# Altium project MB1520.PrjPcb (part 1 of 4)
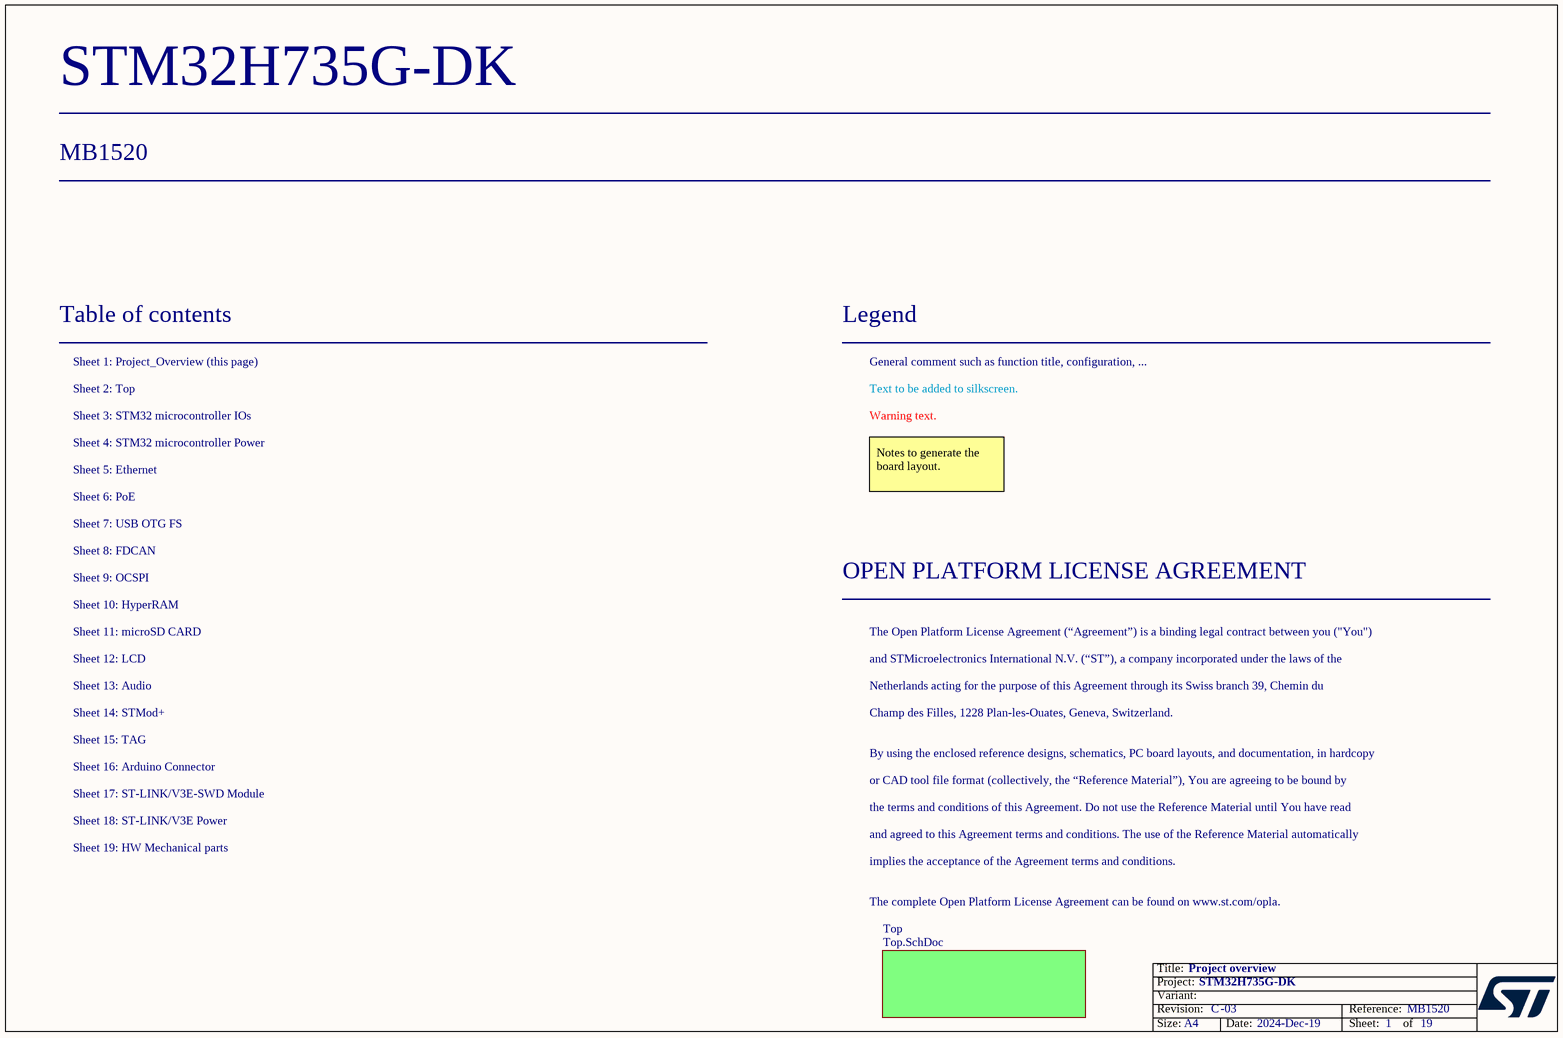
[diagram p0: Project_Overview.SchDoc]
Board_Reference: MB1520; Board_PCB_Revision: C; Board_Name: STM32H735G-DK; Board_Document_Date: 2024-Dec-19; Board_Assembly_Revision: 03
19 sheets, 477 parts. Net scope: flat (ports and power ports of the same name join across sheets).
Board file: MB1520.PcbDoc
Sheets:
  Project_Overview.SchDoc
    Top = Top.SchDoc
      Power = STM32_microcontroller_Power.SchDoc
      TAG = TAG.SchDoc
      Audio = Audio.SchDoc
      USB_OTG_FS = USB_OTG_FS.SchDoc
      Arduino = Arduino_Connector.SchDoc
      STMod+ = STMod+.SchDoc
      U_MCU = STM32_microcontroller_IOs.SchDoc
      U_Ethernet = Ethernet.SchDoc
        PoE = PoE.SchDoc
      FDCANs = FDCAN.SchDoc
      STlink_V3E_Module = STlink_V3E_Module.SchDoc
      STlink_V3E_PWR = STlink_V3E_PWR.SchDoc
      HW_Mechanical_Parts = HW_Mechanical_Parts.SchDoc
      U_OCSPI = OCSPI.SchDoc
      U_LCD = LCD.SchDoc
      U_HyperRAM = HyperRAM.SchDoc
      U_SD CARD = SD_CARD.SchDoc

## Sheet Project_Overview.SchDoc: Project overview
size A4; Date: Not used; ApprovedBy: Not used; CheckedBy: Not used; Author: Not used; CompanyName: STMicroelectronics; DrawnBy: Not used; Engineer: Not used; Organization: Not used; Address1: Not used; Address2: Not used; Address3: Not used; Address4: Not used; DocumentNumber: Not used; Revision: Not used; SheetNumber: 1; SheetTotal: 19

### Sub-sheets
Top = Top.SchDoc: no entries

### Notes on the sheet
- Table of contents
- Sheet 1: Project_Overview (this page)
- Legend
- General comment such as function title, configuration, ...
- Sheet 2: Top
- Sheet 4: STM32 microcontroller Power
- Sheet 3: STM32 microcontroller IOs
- Text to be added to silkscreen.
- Warning text.
- Sheet 6: PoE
- Sheet 5: Ethernet
- Notes to generate the board layout.
- Sheet 8: FDCAN
- Sheet 7: USB OTG FS
- Sheet 9: OCSPI
- OPEN PLATFORM LICENSE AGREEMENT
- Sheet 10: HyperRAM
- Sheet 11: microSD CARD
- The Open Platform License Agreement (“Agreement”) is a binding legal contract between you ("You")
- Sheet 12: LCD
- Sheet 14: STMod+
- Sheet 13: Audio
- and STMicroelectronics International N.V. (“ST”), a company incorporated under the laws of the
- Netherlands acting for the purpose of this Agreement through its Swiss branch 39, Chemin du
- Champ des Filles, 1228 Plan-les-Ouates, Geneva, Switzerland.
- Sheet 16: Arduino Connector
- Sheet 15: TAG
- By using the enclosed reference designs, schematics, PC board layouts, and documentation, in hardcopy
- or CAD tool file format (collectively, the “Reference Material”), You are agreeing to be bound by
- Sheet 18: ST-LINK/V3E Power
- Sheet 17: ST-LINK/V3E-SWD Module
- Sheet 19: HW Mechanical parts
- the terms and conditions of this Agreement. Do not use the Reference Material until You have read
- and agreed to this Agreement terms and conditions. The use of the Reference Material automatically
- implies the acceptance of the Agreement terms and conditions.
- The complete Open Platform License Agreement can be found on www.st.com/opla.

## Sheet Top.SchDoc: TOP
size A3; Date: Not used; ApprovedBy: Not used; CheckedBy: Not used; Author: Not used; CompanyName: STMicroelectronics; DrawnBy: Not used; Engineer: Not used; Organization: Not used; Address1: Not used; Address2: Not used; Address3: Not used; Address4: Not used; DocumentNumber: Not used; Revision: Not used; SheetNumber: 2; SheetTotal: 19
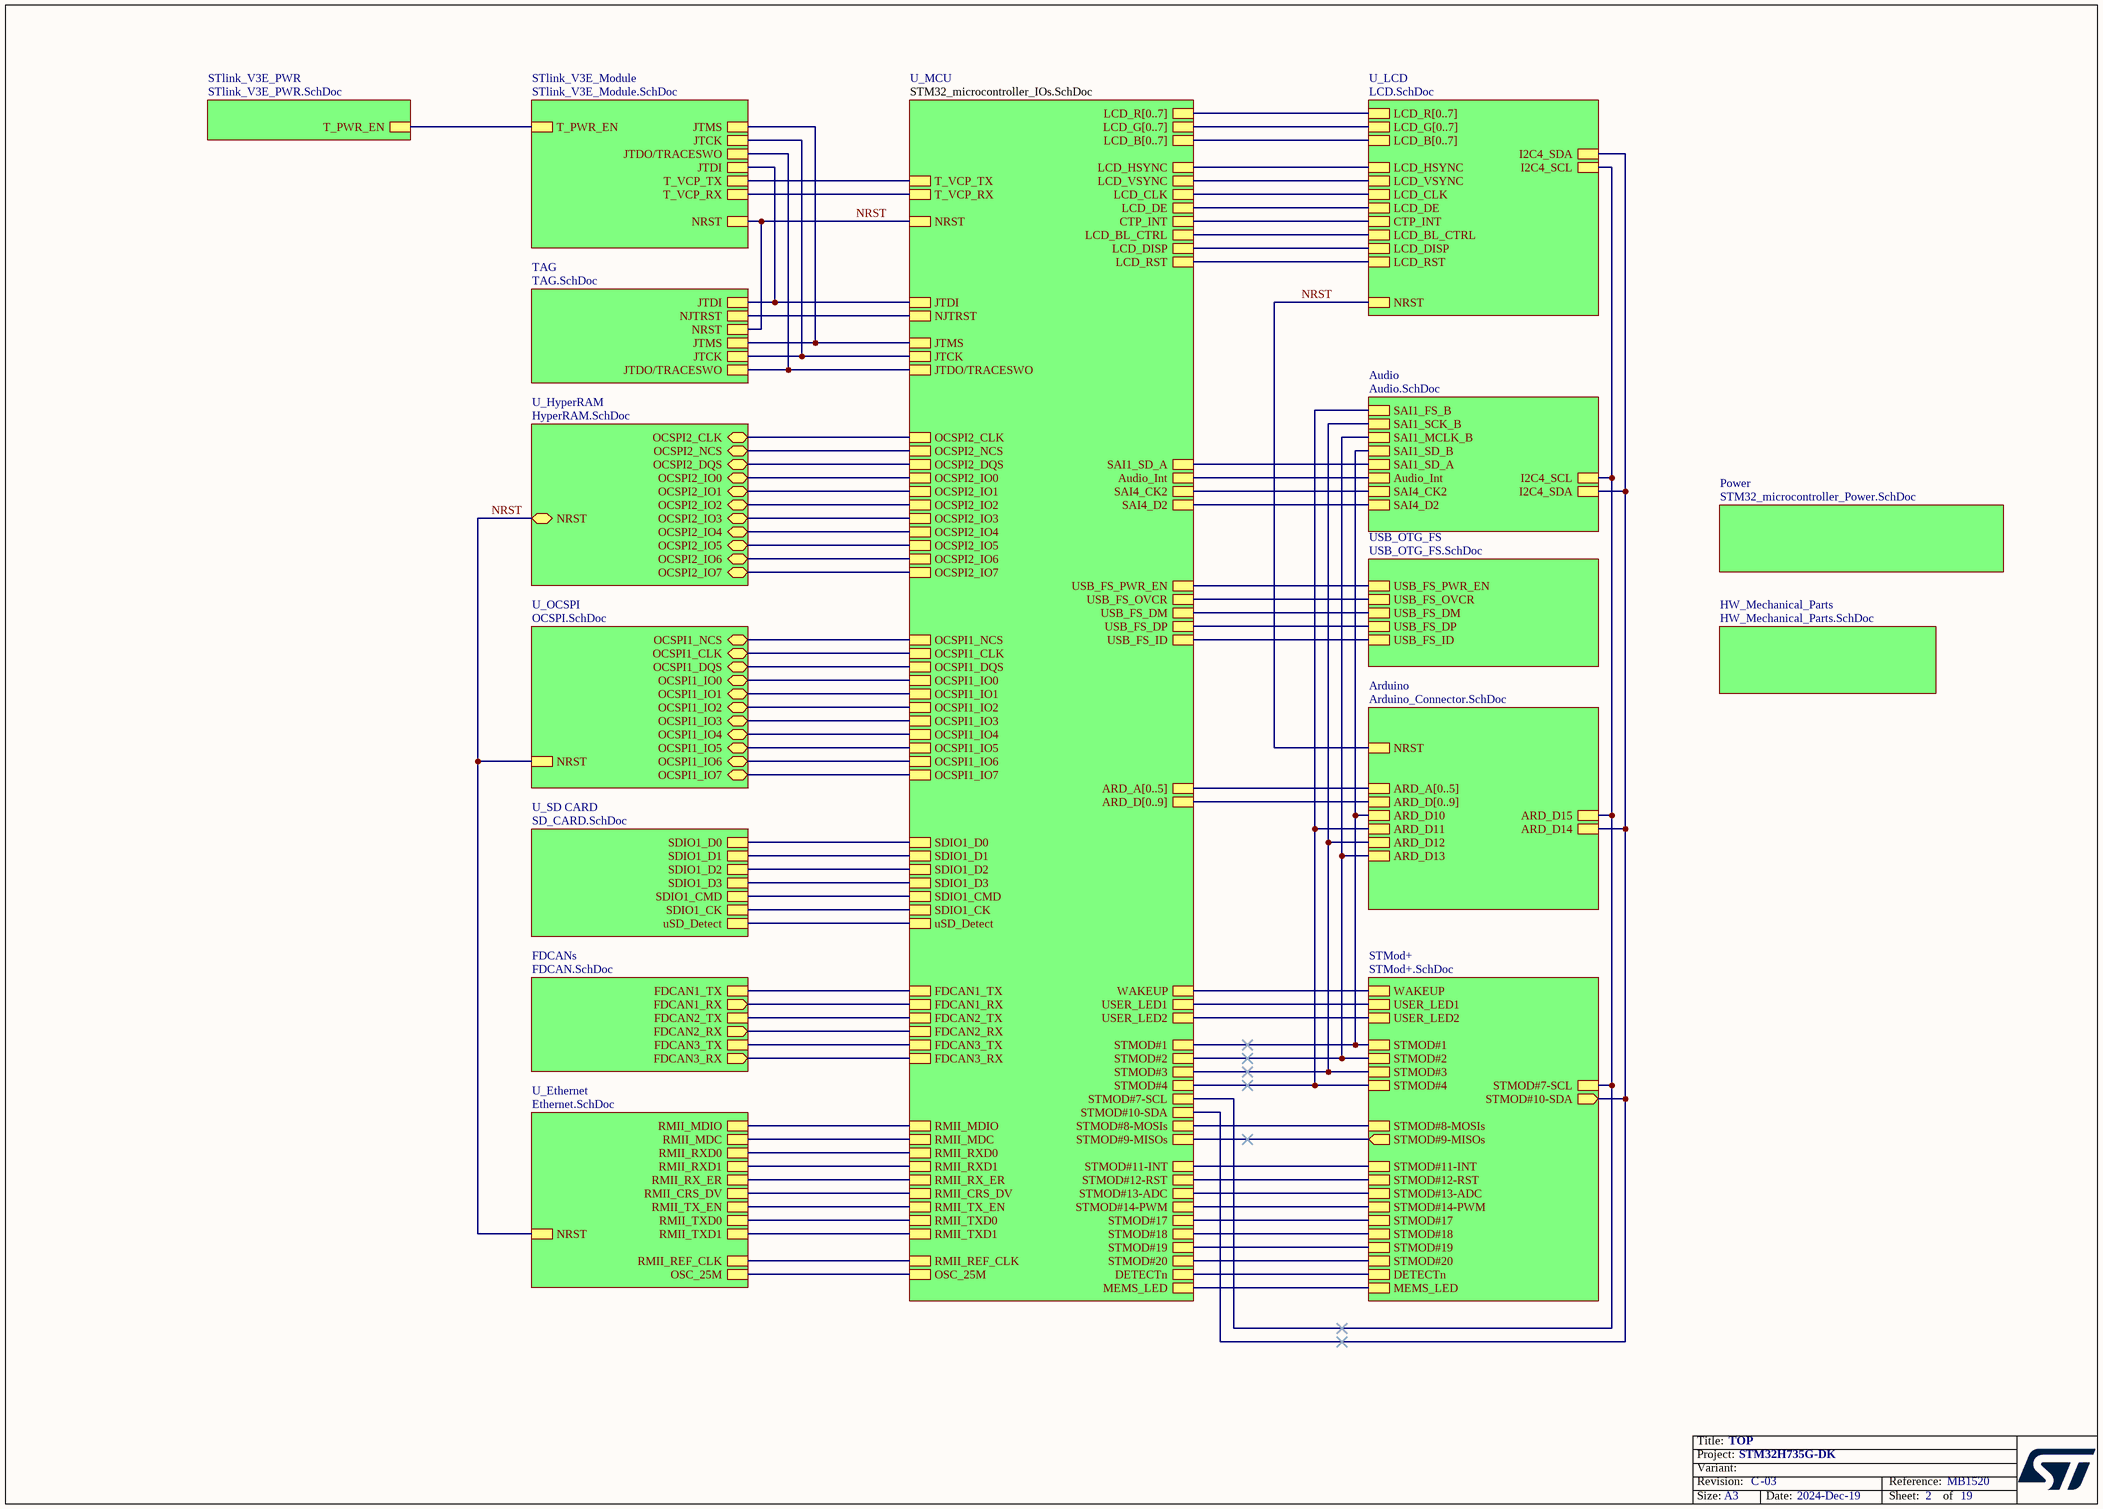
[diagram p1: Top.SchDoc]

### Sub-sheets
Arduino = Arduino_Connector.SchDoc: ARD_D13, ARD_D12, ARD_D11, ARD_D10, ARD_D15, ARD_D14, ARD_A[0..5], ARD_D[0..9], NRST
Audio = Audio.SchDoc: I2C4_SCL, I2C4_SDA, SAI1_SCK_B, SAI1_FS_B, SAI1_SD_B, SAI1_SD_A, Audio_Int, SAI1_MCLK_B, SAI4_D2, SAI4_CK2
FDCANs = FDCAN.SchDoc: FDCAN1_TX, FDCAN2_TX, FDCAN3_TX, FDCAN1_RX (out), FDCAN3_RX (out), FDCAN2_RX (out)
HW_Mechanical_Parts = HW_Mechanical_Parts.SchDoc: no entries
Power = STM32_microcontroller_Power.SchDoc: no entries
STlink_V3E_Module = STlink_V3E_Module.SchDoc: T_PWR_EN, T_VCP_TX, T_VCP_RX, JTDO/TRACESWO, JTMS, JTCK, NRST, JTDI
STlink_V3E_PWR = STlink_V3E_PWR.SchDoc: T_PWR_EN
STMod+ = STMod+.SchDoc: STMOD#8-MOSIs, STMOD#14-PWM, STMOD#19, STMOD#20, STMOD#17, STMOD#18, STMOD#1, STMOD#3, STMOD#2, STMOD#4, WAKEUP, USER_LED1, USER_LED2, STMOD#7-SCL, STMOD#10-SDA (out), STMOD#9-MISOs (out), STMOD#12-RST, STMOD#13-ADC, STMOD#11-INT, DETECTn, MEMS_LED
TAG = TAG.SchDoc: JTDO/TRACESWO, JTDI, NJTRST, JTMS, JTCK, NRST
U_Ethernet = Ethernet.SchDoc: OSC_25M, RMII_MDIO, RMII_MDC, RMII_RXD1, RMII_TXD1, RMII_CRS_DV, RMII_RX_ER, RMII_RXD0, RMII_REF_CLK, RMII_TX_EN, RMII_TXD0, NRST
U_HyperRAM = HyperRAM.SchDoc: OCSPI2_NCS (bidir), NRST (bidir), OCSPI2_CLK (bidir), OCSPI2_DQS (bidir), OCSPI2_IO0 (bidir), OCSPI2_IO3 (bidir), OCSPI2_IO1 (bidir), OCSPI2_IO2 (bidir), OCSPI2_IO5 (bidir), OCSPI2_IO4 (bidir), OCSPI2_IO7 (bidir), OCSPI2_IO6 (bidir)
U_LCD = LCD.SchDoc: LCD_R[0..7], I2C4_SDA, I2C4_SCL, LCD_B[0..7], LCD_G[0..7], LCD_HSYNC, LCD_VSYNC, LCD_CLK, LCD_DE, CTP_INT, LCD_BL_CTRL, LCD_DISP, NRST, LCD_RST
U_MCU = STM32_microcontroller_IOs.SchDoc: STMOD#14-PWM, STMOD#20, USB_FS_ID, SDIO1_CK, SDIO1_CMD, LCD_DE, LCD_CLK, CTP_INT, USER_LED1, USER_LED2, ARD_A[0..5], ARD_D[0..9], LCD_R[0..7], LCD_G[0..7], LCD_B[0..7], FDCAN3_RX, FDCAN3_TX, T_VCP_TX, T_VCP_RX, FDCAN2_RX, FDCAN2_TX, FDCAN1_TX, FDCAN1_RX, LCD_DISP, LCD_VSYNC, LCD_BL_CTRL, LCD_HSYNC, JTDI, JTDO/TRACESWO, NJTRST, JTCK, JTMS, OCSPI2_NCS, OCSPI1_DQS, OCSPI1_NCS, OCSPI1_CLK, OCSPI2_DQS, OSC_25M, USB_FS_DP, USB_FS_DM, USB_FS_OVCR, USB_FS_PWR_EN, WAKEUP, SAI1_SD_A, SAI4_D2, SAI4_CK2, Audio_Int, STMOD#1, STMOD#2, STMOD#3, STMOD#4, STMOD#19, STMOD#17, STMOD#18, STMOD#10-SDA, STMOD#7-SCL, STMOD#8-MOSIs, STMOD#9-MISOs, STMOD#11-INT, STMOD#13-ADC, STMOD#12-RST, MEMS_LED, DETECTn, uSD_Detect, RMII_RXD1, RMII_RXD0, RMII_CRS_DV, RMII_RX_ER, RMII_TX_EN, RMII_TXD0, RMII_TXD1, RMII_MDIO, RMII_MDC, RMII_REF_CLK, SDIO1_D1, SDIO1_D0, SDIO1_D2, SDIO1_D3, OCSPI2_CLK, NRST, OCSPI1_IO7, OCSPI1_IO4, OCSPI1_IO5, OCSPI1_IO0, OCSPI1_IO1, OCSPI1_IO3, OCSPI1_IO2, OCSPI1_IO6, OCSPI2_IO7, OCSPI2_IO6, OCSPI2_IO5, OCSPI2_IO0, OCSPI2_IO2, OCSPI2_IO1, OCSPI2_IO4, OCSPI2_IO3, LCD_RST
U_OCSPI = OCSPI.SchDoc: OCSPI1_NCS (bidir), OCSPI1_CLK (bidir), NRST, OCSPI1_DQS (bidir), OCSPI1_IO0 (bidir), OCSPI1_IO1 (bidir), OCSPI1_IO2 (bidir), OCSPI1_IO3 (bidir), OCSPI1_IO4 (bidir), OCSPI1_IO5 (bidir), OCSPI1_IO6 (bidir), OCSPI1_IO7 (bidir)
U_SD CARD = SD_CARD.SchDoc: SDIO1_CK, SDIO1_CMD, uSD_Detect, SDIO1_D1, SDIO1_D0, SDIO1_D2, SDIO1_D3
USB_OTG_FS = USB_OTG_FS.SchDoc: USB_FS_ID, USB_FS_PWR_EN, USB_FS_OVCR, USB_FS_DM, USB_FS_DP

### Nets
NRST: sheet TAG/NRST, sheet Arduino/NRST, sheet U_MCU/NRST, sheet U_Ethernet/NRST, sheet STlink_V3E_Module/NRST, sheet U_OCSPI/NRST, sheet U_LCD/NRST, sheet U_HyperRAM/NRST
(unnamed): sheet TAG/JTDO/TRACESWO, sheet U_MCU/JTDO/TRACESWO, sheet STlink_V3E_Module/JTDO/TRACESWO
(unnamed): sheet TAG/JTDI, sheet U_MCU/JTDI, sheet STlink_V3E_Module/JTDI  [a separate net that carries the same name]
(unnamed): sheet TAG/NJTRST, sheet U_MCU/NJTRST  [a separate net that carries the same name]
(unnamed): sheet TAG/JTMS, sheet U_MCU/JTMS, sheet STlink_V3E_Module/JTMS  [a separate net that carries the same name]
(unnamed): sheet TAG/JTCK, sheet U_MCU/JTCK, sheet STlink_V3E_Module/JTCK  [a separate net that carries the same name]
(unnamed): sheet Audio/I2C4_SCL, sheet Arduino/ARD_D15, sheet STMod+/STMOD#7-SCL, sheet U_MCU/STMOD#7-SCL, sheet U_LCD/I2C4_SCL  [a separate net that carries the same name]
(unnamed): sheet Audio/I2C4_SDA, sheet Arduino/ARD_D14, sheet STMod+/STMOD#10-SDA, sheet U_MCU/STMOD#10-SDA, sheet U_LCD/I2C4_SDA  [a separate net that carries the same name]
(unnamed): sheet Audio/SAI1_SCK_B, sheet Arduino/ARD_D12, sheet STMod+/STMOD#3, sheet U_MCU/STMOD#3  [a separate net that carries the same name]
(unnamed): sheet Audio/SAI1_FS_B, sheet Arduino/ARD_D11, sheet STMod+/STMOD#4, sheet U_MCU/STMOD#4  [a separate net that carries the same name]
(unnamed): sheet Audio/SAI1_SD_B, sheet Arduino/ARD_D10, sheet STMod+/STMOD#1, sheet U_MCU/STMOD#1  [a separate net that carries the same name]
(unnamed): sheet Audio/SAI1_SD_A, sheet U_MCU/SAI1_SD_A  [a separate net that carries the same name]
(unnamed): sheet Audio/Audio_Int, sheet U_MCU/Audio_Int  [a separate net that carries the same name]
(unnamed): sheet Audio/SAI1_MCLK_B, sheet Arduino/ARD_D13, sheet STMod+/STMOD#2, sheet U_MCU/STMOD#2  [a separate net that carries the same name]
(unnamed): sheet Audio/SAI4_D2, sheet U_MCU/SAI4_D2  [a separate net that carries the same name]
(unnamed): sheet Audio/SAI4_CK2, sheet U_MCU/SAI4_CK2  [a separate net that carries the same name]
(unnamed): sheet USB_OTG_FS/USB_FS_ID, sheet U_MCU/USB_FS_ID  [a separate net that carries the same name]
(unnamed): sheet USB_OTG_FS/USB_FS_PWR_EN, sheet U_MCU/USB_FS_PWR_EN  [a separate net that carries the same name]
(unnamed): sheet USB_OTG_FS/USB_FS_OVCR, sheet U_MCU/USB_FS_OVCR  [a separate net that carries the same name]
(unnamed): sheet USB_OTG_FS/USB_FS_DM, sheet U_MCU/USB_FS_DM  [a separate net that carries the same name]
(unnamed): sheet USB_OTG_FS/USB_FS_DP, sheet U_MCU/USB_FS_DP  [a separate net that carries the same name]
(unnamed): sheet STMod+/STMOD#8-MOSIs, sheet U_MCU/STMOD#8-MOSIs  [a separate net that carries the same name]
(unnamed): sheet STMod+/STMOD#14-PWM, sheet U_MCU/STMOD#14-PWM  [a separate net that carries the same name]
(unnamed): sheet STMod+/STMOD#19, sheet U_MCU/STMOD#19  [a separate net that carries the same name]
(unnamed): sheet STMod+/STMOD#20, sheet U_MCU/STMOD#20  [a separate net that carries the same name]
(unnamed): sheet STMod+/STMOD#17, sheet U_MCU/STMOD#17  [a separate net that carries the same name]
(unnamed): sheet STMod+/STMOD#18, sheet U_MCU/STMOD#18  [a separate net that carries the same name]
(unnamed): sheet STMod+/WAKEUP, sheet U_MCU/WAKEUP  [a separate net that carries the same name]
(unnamed): sheet STMod+/USER_LED1, sheet U_MCU/USER_LED1  [a separate net that carries the same name]
(unnamed): sheet STMod+/USER_LED2, sheet U_MCU/USER_LED2  [a separate net that carries the same name]
(unnamed): sheet STMod+/STMOD#9-MISOs, sheet U_MCU/STMOD#9-MISOs  [a separate net that carries the same name]
(unnamed): sheet STMod+/STMOD#12-RST, sheet U_MCU/STMOD#12-RST  [a separate net that carries the same name]
(unnamed): sheet STMod+/STMOD#13-ADC, sheet U_MCU/STMOD#13-ADC  [a separate net that carries the same name]
(unnamed): sheet STMod+/STMOD#11-INT, sheet U_MCU/STMOD#11-INT  [a separate net that carries the same name]
(unnamed): sheet STMod+/DETECTn, sheet U_MCU/DETECTn  [a separate net that carries the same name]
(unnamed): sheet STMod+/MEMS_LED, sheet U_MCU/MEMS_LED  [a separate net that carries the same name]
(unnamed): sheet U_MCU/SDIO1_CK, sheet U_SD CARD/SDIO1_CK  [a separate net that carries the same name]
(unnamed): sheet U_MCU/SDIO1_CMD, sheet U_SD CARD/SDIO1_CMD  [a separate net that carries the same name]
(unnamed): sheet U_MCU/LCD_DE, sheet U_LCD/LCD_DE  [a separate net that carries the same name]
(unnamed): sheet U_MCU/LCD_CLK, sheet U_LCD/LCD_CLK  [a separate net that carries the same name]
(unnamed): sheet U_MCU/CTP_INT, sheet U_LCD/CTP_INT  [a separate net that carries the same name]
(unnamed): sheet U_MCU/FDCAN3_RX, sheet FDCANs/FDCAN3_RX  [a separate net that carries the same name]
(unnamed): sheet U_MCU/FDCAN3_TX, sheet FDCANs/FDCAN3_TX  [a separate net that carries the same name]
(unnamed): sheet U_MCU/T_VCP_TX, sheet STlink_V3E_Module/T_VCP_TX  [a separate net that carries the same name]
(unnamed): sheet U_MCU/T_VCP_RX, sheet STlink_V3E_Module/T_VCP_RX  [a separate net that carries the same name]
(unnamed): sheet U_MCU/FDCAN2_RX, sheet FDCANs/FDCAN2_RX  [a separate net that carries the same name]
(unnamed): sheet U_MCU/FDCAN2_TX, sheet FDCANs/FDCAN2_TX  [a separate net that carries the same name]
(unnamed): sheet U_MCU/FDCAN1_TX, sheet FDCANs/FDCAN1_TX  [a separate net that carries the same name]
(unnamed): sheet U_MCU/FDCAN1_RX, sheet FDCANs/FDCAN1_RX  [a separate net that carries the same name]
(unnamed): sheet U_MCU/LCD_DISP, sheet U_LCD/LCD_DISP  [a separate net that carries the same name]
(unnamed): sheet U_MCU/LCD_VSYNC, sheet U_LCD/LCD_VSYNC  [a separate net that carries the same name]
(unnamed): sheet U_MCU/LCD_BL_CTRL, sheet U_LCD/LCD_BL_CTRL  [a separate net that carries the same name]
(unnamed): sheet U_MCU/LCD_HSYNC, sheet U_LCD/LCD_HSYNC  [a separate net that carries the same name]
(unnamed): sheet U_MCU/OCSPI2_NCS, sheet U_HyperRAM/OCSPI2_NCS  [a separate net that carries the same name]
(unnamed): sheet U_MCU/OCSPI1_DQS, sheet U_OCSPI/OCSPI1_DQS  [a separate net that carries the same name]
(unnamed): sheet U_MCU/OCSPI1_NCS, sheet U_OCSPI/OCSPI1_NCS  [a separate net that carries the same name]
(unnamed): sheet U_MCU/OCSPI1_CLK, sheet U_OCSPI/OCSPI1_CLK  [a separate net that carries the same name]
(unnamed): sheet U_MCU/OCSPI2_DQS, sheet U_HyperRAM/OCSPI2_DQS  [a separate net that carries the same name]
(unnamed): sheet U_MCU/OSC_25M, sheet U_Ethernet/OSC_25M  [a separate net that carries the same name]
(unnamed): sheet U_MCU/uSD_Detect, sheet U_SD CARD/uSD_Detect  [a separate net that carries the same name]
(unnamed): sheet U_MCU/RMII_RXD1, sheet U_Ethernet/RMII_RXD1  [a separate net that carries the same name]
(unnamed): sheet U_MCU/RMII_RXD0, sheet U_Ethernet/RMII_RXD0  [a separate net that carries the same name]
(unnamed): sheet U_MCU/RMII_CRS_DV, sheet U_Ethernet/RMII_CRS_DV  [a separate net that carries the same name]
(unnamed): sheet U_MCU/RMII_RX_ER, sheet U_Ethernet/RMII_RX_ER  [a separate net that carries the same name]
(unnamed): sheet U_MCU/RMII_TX_EN, sheet U_Ethernet/RMII_TX_EN  [a separate net that carries the same name]
(unnamed): sheet U_MCU/RMII_TXD0, sheet U_Ethernet/RMII_TXD0  [a separate net that carries the same name]
(unnamed): sheet U_MCU/RMII_TXD1, sheet U_Ethernet/RMII_TXD1  [a separate net that carries the same name]
(unnamed): sheet U_MCU/RMII_MDIO, sheet U_Ethernet/RMII_MDIO  [a separate net that carries the same name]
(unnamed): sheet U_MCU/RMII_MDC, sheet U_Ethernet/RMII_MDC  [a separate net that carries the same name]
(unnamed): sheet U_MCU/RMII_REF_CLK, sheet U_Ethernet/RMII_REF_CLK  [a separate net that carries the same name]
(unnamed): sheet U_MCU/SDIO1_D1, sheet U_SD CARD/SDIO1_D1  [a separate net that carries the same name]
(unnamed): sheet U_MCU/SDIO1_D0, sheet U_SD CARD/SDIO1_D0  [a separate net that carries the same name]
(unnamed): sheet U_MCU/SDIO1_D2, sheet U_SD CARD/SDIO1_D2  [a separate net that carries the same name]
(unnamed): sheet U_MCU/SDIO1_D3, sheet U_SD CARD/SDIO1_D3  [a separate net that carries the same name]
(unnamed): sheet U_MCU/OCSPI2_CLK, sheet U_HyperRAM/OCSPI2_CLK  [a separate net that carries the same name]
(unnamed): sheet U_MCU/OCSPI1_IO7, sheet U_OCSPI/OCSPI1_IO7  [a separate net that carries the same name]
(unnamed): sheet U_MCU/OCSPI1_IO4, sheet U_OCSPI/OCSPI1_IO4  [a separate net that carries the same name]
(unnamed): sheet U_MCU/OCSPI1_IO5, sheet U_OCSPI/OCSPI1_IO5  [a separate net that carries the same name]
(unnamed): sheet U_MCU/OCSPI1_IO0, sheet U_OCSPI/OCSPI1_IO0  [a separate net that carries the same name]
(unnamed): sheet U_MCU/OCSPI1_IO1, sheet U_OCSPI/OCSPI1_IO1  [a separate net that carries the same name]
(unnamed): sheet U_MCU/OCSPI1_IO3, sheet U_OCSPI/OCSPI1_IO3  [a separate net that carries the same name]
(unnamed): sheet U_MCU/OCSPI1_IO2, sheet U_OCSPI/OCSPI1_IO2  [a separate net that carries the same name]
(unnamed): sheet U_MCU/OCSPI1_IO6, sheet U_OCSPI/OCSPI1_IO6  [a separate net that carries the same name]
(unnamed): sheet U_MCU/OCSPI2_IO7, sheet U_HyperRAM/OCSPI2_IO7  [a separate net that carries the same name]
(unnamed): sheet U_MCU/OCSPI2_IO6, sheet U_HyperRAM/OCSPI2_IO6  [a separate net that carries the same name]
(unnamed): sheet U_MCU/OCSPI2_IO5, sheet U_HyperRAM/OCSPI2_IO5  [a separate net that carries the same name]
(unnamed): sheet U_MCU/OCSPI2_IO0, sheet U_HyperRAM/OCSPI2_IO0  [a separate net that carries the same name]
(unnamed): sheet U_MCU/OCSPI2_IO2, sheet U_HyperRAM/OCSPI2_IO2  [a separate net that carries the same name]
(unnamed): sheet U_MCU/OCSPI2_IO1, sheet U_HyperRAM/OCSPI2_IO1  [a separate net that carries the same name]
(unnamed): sheet U_MCU/OCSPI2_IO4, sheet U_HyperRAM/OCSPI2_IO4  [a separate net that carries the same name]
(unnamed): sheet U_MCU/OCSPI2_IO3, sheet U_HyperRAM/OCSPI2_IO3  [a separate net that carries the same name]
(unnamed): sheet U_MCU/LCD_RST, sheet U_LCD/LCD_RST  [a separate net that carries the same name]
(unnamed): sheet STlink_V3E_Module/T_PWR_EN, sheet STlink_V3E_PWR/T_PWR_EN  [a separate net that carries the same name]

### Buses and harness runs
bus sheet Arduino/ARD_A[0..5] = sheet U_MCU/ARD_A[0..5]
bus sheet Arduino/ARD_D[0..9] = sheet U_MCU/ARD_D[0..9]
bus sheet U_LCD/LCD_B[0..7] = sheet U_MCU/LCD_B[0..7]
bus sheet U_LCD/LCD_G[0..7] = sheet U_MCU/LCD_G[0..7]
bus sheet U_LCD/LCD_R[0..7] = sheet U_MCU/LCD_R[0..7]

## Sheet STM32_microcontroller_Power.SchDoc: STM32 microcontroller Power
size A4; Date: Not used; ApprovedBy: Not used; CheckedBy: Not used; Author: Not used; CompanyName: STMicroelectronics; DrawnBy: Not used; Engineer: Not used; Organization: Not used; Address1: Not used; Address2: Not used; Address3: Not used; Address4: Not used; DocumentNumber: Not used; Revision: Not used; SheetNumber: 4; SheetTotal: 19
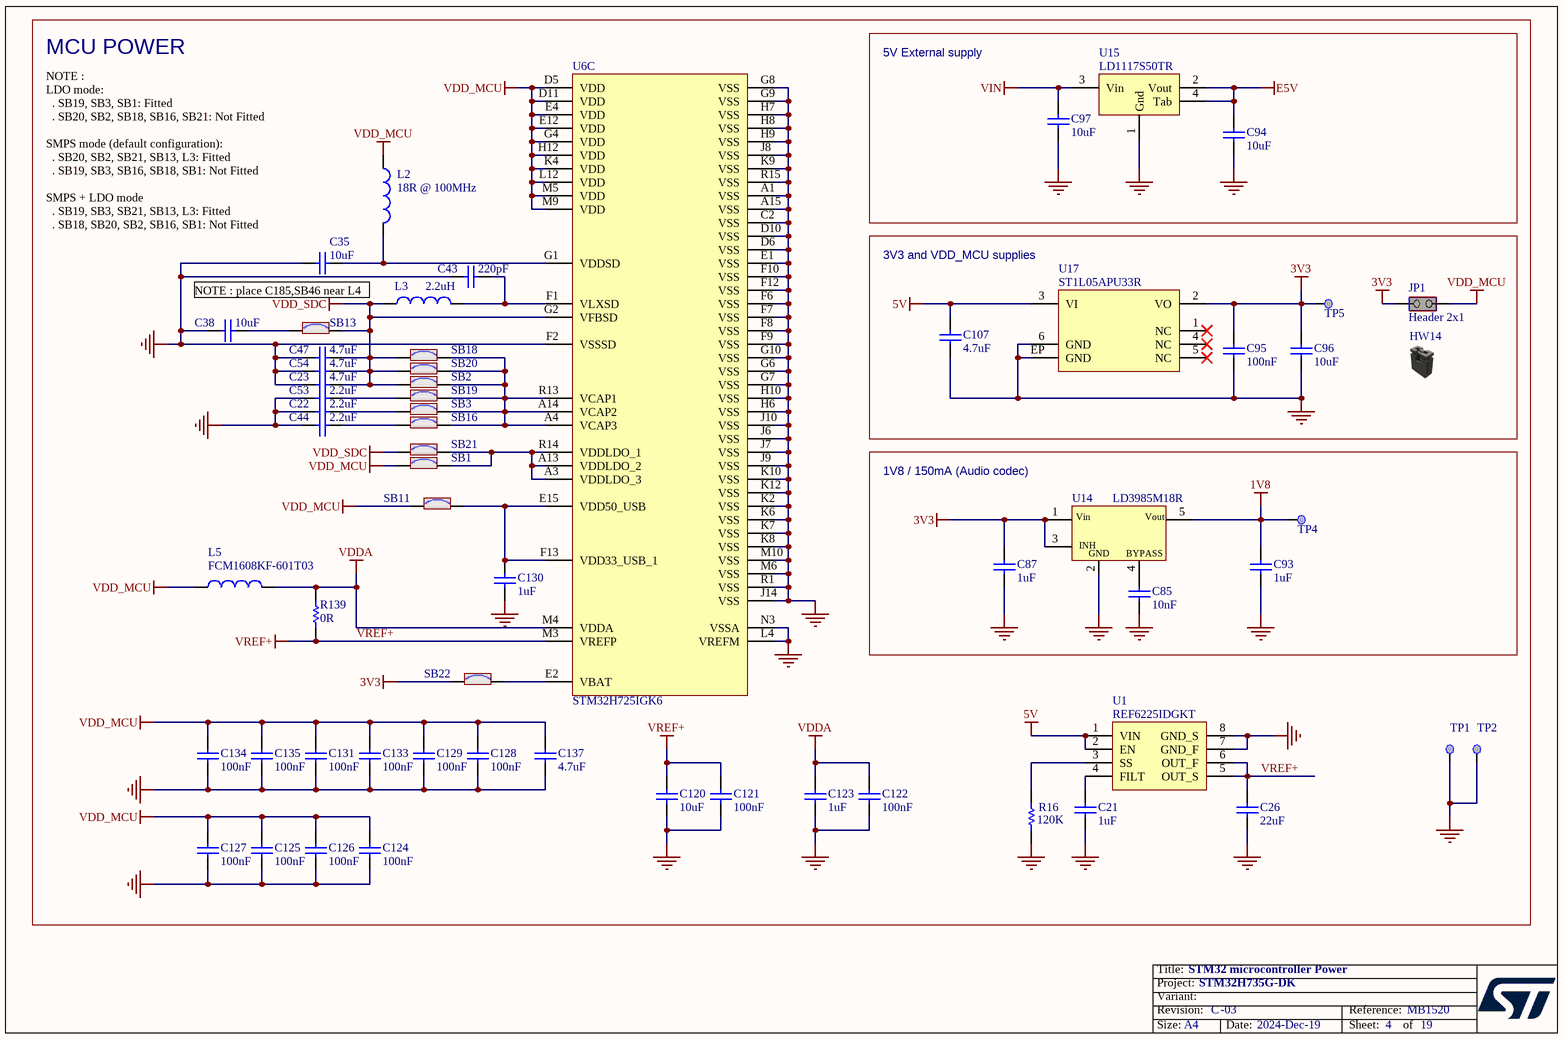
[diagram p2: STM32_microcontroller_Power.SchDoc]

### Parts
C21  value 1uF  [C0603]  (hidden comment: Capacitor)
C22  value 2.2uF  [C0603]  (hidden comment: Capacitor)
C23  value 4.7uF  [C0402]  (hidden comment: Capacitor)
C26  value 22uF  [C1210]  (hidden comment: Capacitor)
C35  value 10uF  [C0402]  (hidden comment: Capacitor)
C38  value 10uF  [C0603]  (hidden comment: Capacitor)
C43  value 220pF  [C0402]  (hidden comment: Capacitor)
C44  value 2.2uF  [C0603]  (hidden comment: Capacitor)
C47  value 4.7uF  [C0402]  (hidden comment: Capacitor)
C53  value 2.2uF  [C0603]  (hidden comment: Capacitor)
C54  value 4.7uF  [C0402]  (hidden comment: Capacitor)
C85  value 10nF  [C0402]  (hidden comment: Capacitor)
C87  value 1uF  [C0402]  (hidden comment: Capacitor)
C93  value 1uF  [C0402]  (hidden comment: Capacitor)
C94  value 10uF  [C0805]  (hidden comment: Capacitor)
C95  value 100nF  [C0402]  (hidden comment: Capacitor)
C96  value 10uF  [C0805]  (hidden comment: Capacitor)
C97  value 10uF  [C0805]  (hidden comment: Capacitor)
C107  value 4.7uF  [C0603]  (hidden comment: Capacitor)
C120  value 10uF  [C0805]  (hidden comment: Capacitor)
C121  value 100nF  [C0402]  (hidden comment: Capacitor)
C122  value 100nF  [C0402]  (hidden comment: Capacitor)
C123  value 1uF  [C0402]  (hidden comment: Capacitor)
C124  value 100nF  [C0402]  (hidden comment: Capacitor)
C125  value 100nF  [C0402]  (hidden comment: Capacitor)
C126  value 100nF  [C0402]  (hidden comment: Capacitor)
C127  value 100nF  [C0402]  (hidden comment: Capacitor)
C128  value 100nF  [C0402]  (hidden comment: Capacitor)
C129  value 100nF  [C0402]  (hidden comment: Capacitor)
C130  value 1uF  [C0603]  (hidden comment: Capacitor)
C131  value 100nF  [C0402]  (hidden comment: Capacitor)
C133  value 100nF  [C0402]  (hidden comment: Capacitor)
C134  value 100nF  [C0402]  (hidden comment: Capacitor)
C135  value 100nF  [C0402]  (hidden comment: Capacitor)
C137  value 4.7uF  [C0402]  (hidden comment: Capacitor)
HW14  Shunt Black 2.54mm  (value not drawn)  (mechanical)
JP1  value Header 2x1  [CON_SAMTEC_TSW-102-07-G-S]  (hidden comment: Jumper_Header 2x1 Fitted)
L2  value 18R @ 100MHz  [IND_0603_LSMCA_H1P0]  (hidden comment: Inductor)
L3  value 2.2uH  [IND_2016_MURATA_LQM2MPN2R2NG0]  (hidden comment: Inductor)
L5  Manufacturer_Part_Number: FCM1608KF-601T03  [L0603]  (hidden comment: BEAD)
R16  value 120K  [R0402]  (hidden comment: Resistor)
R139  value 0R  [R0603]  (hidden comment: Resistor)
SB1  SB_ON  [SOLDER-BRIDGE_R0603-0R]  (value not drawn)
SB2  SB_ON  [SOLDER-BRIDGE_R0603-0R]  (value not drawn)
SB3  SB_ON  [SOLDER-BRIDGE_R0603-0R]  (value not drawn)
SB11  SB_ON  [SOLDER-BRIDGE_R0603-0R]  (value not drawn)
SB13  SB_ON  [SOLDER-BRIDGE_R0603-0R]  (value not drawn)
SB16  SB_ON  [SOLDER-BRIDGE_R0603-0R]  (value not drawn)
SB18  SB_ON  [SOLDER-BRIDGE_R0603-0R]  (value not drawn)
SB19  SB_ON  [SOLDER-BRIDGE_R0603-0R]  (value not drawn)
SB20  SB_ON  [SOLDER-BRIDGE_R0603-0R]  (value not drawn)
SB21  SB_ON  [SOLDER-BRIDGE_R0603-0R]  (value not drawn)
SB22  SB_ON  [SOLDER-BRIDGE_R0603-0R]  (value not drawn)
TP1  Test Point  [TP_SMD_0-3MM]  (value not drawn)  (no BOM)
TP2  Test Point  [TP_SMD_0-3MM]  (value not drawn)  (no BOM)
TP4  Test Point  [TP_SMD_0-3MM]  (value not drawn)  (no BOM)
TP5  Test Point  [TP_SMD_0-3MM]  (value not drawn)  (no BOM)
U1  REF6225IDGKT  [ICC_VSSOP8_DGK_S-PDSO-G8_3X3_P065]
U6  value STM32H725IGK6  [ICC_UFBGA201_176+25_10X10_P065]  (hidden comment: STM32H725IGK6U)  (part C of 3)
U14  LD3985M18R  [REG_SOT23-5L]
U15  LD1117S50TR  [REG_SOT223-TAB]
U17  ST1L05APU33R  [ICC_DFN6-EPAD_3X3_P095]

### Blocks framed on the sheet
5V External supply: C94 C97 U15
3V3 and VDD_MCU supplies: C95 C96 C107 HW14 JP1 TP5 U17
1V8 / 150mA (Audio codec): C85 C87 C93 TP4 U14

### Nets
1V8: C93.2 TP4.1 U14.5(Vout)
3V3: C87.2 C95.1 C96.2 JP1.2(NO) SB22.1 TP5.1 U14.1(Vin) U14.3(CE) U17.2(VO)
5V: C107.2 U1.1(VIN) U1.2(EN) U17.3(VI)
E5V: C94.2 U15.2(Vout) U15.4(Tab)
GND: C21.1 C22.1 C23.2 C26.1 C35.1 C38.1 C43.1 C44.1 C47.2 C53.1 C54.2 C85.1 C87.1 C93.1 C94.1 C95.2 C96.1 C97.1 C107.1 C120.1 C121.1 C122.1 C123.2 C124.1 C125.1 C126.1 C127.1 C128.1 C129.1 C130.2 C131.1 C133.1 C134.1 C135.1 C137.1 R16.1 TP1.1 TP2.1 U1.7(GND_F) U1.8(GND_S) U6.A1(VSS) U6.A15(VSS) U6.C2(VSS) U6.D6(VSS) U6.D10(VSS) U6.E1(VSS) U6.F2(VSSSD) U6.F6(VSS) U6.F7(VSS) U6.F8(VSS) U6.F9(VSS) U6.F10(VSS) U6.F12(VSS) U6.G6(VSS) U6.G7(VSS) U6.G8(VSS) U6.G9(VSS) U6.G10(VSS) U6.H6(VSS) U6.H7(VSS) U6.H8(VSS) U6.H9(VSS) U6.H10(VSS) U6.J6(VSS) U6.J7(VSS) U6.J8(VSS) U6.J9(VSS) U6.J10(VSS) U6.J14(VSS) U6.K2(VSS) U6.K6(VSS) U6.K7(VSS) U6.K8(VSS) U6.K9(VSS) U6.K10(VSS) U6.K12(VSS) U6.L4(VREFM) U6.M6(VSS) U6.M10(VSS) U6.N3(VSSA) U6.R1(VSS) U6.R15(VSS) U14.2(GND) U15.1(Gnd) U17.6(GND) U17.EP(GND)  [project net POE7]
VDD_MCU: C124.2 C125.2 C126.2 C127.2 C128.2 C129.2 C131.2 C133.2 C134.2 C135.2 C137.2 JP1.1(COMMON) L2.1 L5.1 SB1.1 SB11.1 U6.D5(VDD) U6.D11(VDD) U6.E4(VDD) U6.E12(VDD) U6.G4(VDD) U6.H12(VDD) U6.K4(VDD) U6.L12(VDD) U6.M5(VDD) U6.M9(VDD)
VDD_SDC: C23.1 C47.1 C54.1 L3.1 SB2.1 SB13.2 SB18.1 SB20.1 SB21.1 U6.G2(VFBSD)
VDDA: C122.2 C123.1 L5.2 R139.2 U6.M4(VDDA)
VIN: C97.2 U15.3(Vin)
VREF+: C26.2 C120.2 C121.2 R139.1 U1.5(OUT_S) U1.6(OUT_F) U6.M3(VREFP)
NetC21_2: C21.2 U1.4(FILT)
NetC22_2: C22.2 SB3.1
NetC35_2: C35.2 L2.2 U6.G1(VDDSD)
NetC38_2: C38.2 SB13.1
NetC43_2: C43.2 L3.2 U6.F1(VLXSD)
NetC44_2: C44.2 SB16.1
NetC53_2: C53.2 SB19.1
NetC85_2: C85.2 U14.4(BYPASS)
NetC130_1: C130.1 SB11.2 U6.E15(VDD50_USB) U6.F13(VDD33_USB_1)
NetR16_2: R16.2 U1.3(SS)
NetSB1_2: SB1.2 SB21.2 U6.A3(VDDLDO_3) U6.A13(VDDLDO_2) U6.R14(VDDLDO_1)
NetSB2_2: SB2.2 SB3.2 SB16.2 SB18.2 SB19.2 SB20.2 U6.A4(VCAP3) U6.A14(VCAP2) U6.R13(VCAP1)
NetSB22_2: SB22.2 U6.E2(VBAT)

Not connected (* = marked no-connect by the designer): U17 1(NC)* 4(NC)* 5(NC)*

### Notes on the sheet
- MCU POWER
- (near C35) NOTE :
  LDO mode:
  . SB19, SB3, SB1: Fitted
  . SB20, SB2, SB18, SB16, SB21: Not Fitted
  SMPS mode (default configuration):
  . SB20, SB2, SB21, SB13, L3: Fitted
  . SB19, SB3, SB16, SB18, SB1: Not Fitted
  SMPS + LDO mode
  . SB19, SB3, SB21, SB13, L3: Fitted
  . SB18, SB20, SB2, SB16, SB1: Not Fitted
- NOTE : place C185,SB46 near L4

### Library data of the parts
C21 C130 = MCD-00010: Capacitor, MLCC, 1uF, 16V, X5R, 10%, 0603, T=0,8mm; Manufacturer_Part_Number: CC0603KRX5R7BB105; Manufacturer: YAGEO; Part_Preference: Recommended; Provided_By: SUBCO; Component_Country_Of_Origin: China; ID: 2470; ShowFields: YES
C22 C44 C53 = MCD-00012: Capacitor, MLCC, 2.2uF, 10V, X5R, 10%, 0603, T=0,8mm; Manufacturer_Part_Number: CC0603KRX5R6BB225; Manufacturer: YAGEO; Alternate_Manufacturer_Part_Number: C0603C225K8PACTU; Alternate_Manufacturer: KEMET; BMS_Part_Number: 9142010; Part_Preference: Recommended; Provided_By: SUBCO; Component_Country_Of_Origin: China; ID: 2467; ShowFields: YES
C23 C47 C54 = MCD-01356: Capacitor, MLCC, 4.7uF, 6V3, X5R, 20%, 0402, T=0,5mm; Manufacturer_Part_Number: GRM155R60J475ME47; Manufacturer: MURATA; Part_Preference: Recommended; Provided_By: SUBCO; Component_Country_Of_Origin: Japan; ID: 3456; Order_Code_RS: 814-5230; ShowFields: YES
C26 = MCD-00614: Capacitor, MLCC, 22uF, 16V, 1210, X7R, 20%, T=2,5mm, ESR 2mohm@410KHz; Manufacturer_Part_Number: GCM32ER71C226ME19; Manufacturer: MURATA; Part_Preference: Recommended; Provided_By: SUBCO; Component_Country_Of_Origin: Japan; ID: 3130; ShowFields: YES
C35 = MCD-01355: Capacitor, MLCC, 10uF, 4V, X5R, 20%, 0402, T=0,5mm; Manufacturer_Part_Number: GRM155R60G106ME44; Manufacturer: MURATA; Part_Preference: Recommended; Partial_Alternate_Internal_Part_Number: MCD-01716; Provided_By: SUBCO; Alternate_EMS: A; Component_Country_Of_Origin: Japan; ID: 3455; Order_Code_RS: 172-6477; ShowFields: YES
C38 = MCD-01341: Capacitor, MLCC, 10uF, 6V3, X5R, 20%, 0603, T=0,8mm; Manufacturer_Part_Number: GRM188R60J106ME47D; Manufacturer: MURATA; Part_Preference: Recommended; Provided_By: SUBCO; Component_Country_Of_Origin: Japan; ID: 3441; ShowFields: YES
C43 = MCD-01225: Capacitor, MLCC, 220pF, 50V, NPO, 5%, 0402, T=0,5mm; Manufacturer_Part_Number: CC0402JRNPO9BN221; Manufacturer: YAGEO; Part_Preference: Recommended; Provided_By: SUBCO; Component_Country_Of_Origin: China; ID: 3272; Order_Code_RS: 616-9284; ShowFields: YES
C85 = MCD-00011: Capacitor, MLCC, 10nF, 16V, X7R, 10%, 0402, T=0.5mm; Manufacturer_Part_Number: CC0402KRX7R7BB103; Manufacturer: YAGEO; Part_Preference: Recommended; ECCN_US: EAR99; ECCN_EU: NEC; Provided_By: SUBCO; Component_Country_Of_Origin: China; ID: 2469; Order_Code_RS: 669-8688; ShowFields: YES
C87 C93 = MCD-00095: Capacitor, MLCC, 1uF, 6V3, X5R, 10%, 0402, T=0,5mm; Manufacturer_Part_Number: GRM155R61E105KA12; Manufacturer: MURATA; Alternate_Manufacturer_Part_Number: GRM155R60J105KE19; Part_Preference: Recommended; ECCN_US: EAR99; ECCN_EU: NEC; Provided_By: SUBCO; Component_Country_Of_Origin: Japan; ID: 2772; Order_Code_RS: 846-7287; ShowFields: YES
C94 C96 C97 C120 = MCD-00014: Capacitor, MLCC, 10uF, 25V, X5R, 10%, 0805, T=0,85mm; Manufacturer_Part_Number: CC0805KRX5R8BB106; Manufacturer: YAGEO; Full_Alternate_Internal_Part_Number: MCD-02385; Part_Preference: Recommended; Partial_Alternate_Internal_Part_Number: MCD-03053; Provided_By: SUBCO; Component_Country_Of_Origin: China; ID: 2468; ShowFields: YES
C95 C121 C122 C124-C129 C131 C133-C135 = MCD-00006: Capacitor, MLCC, 100nF, 16V, X7R, +/-10%, 0402, T=0.5mm; Manufacturer_Part_Number: CC0402KRX7R7BB104; Manufacturer: YAGEO; Part_Preference: Recommended; Partial_Alternate_Internal_Part_Number: MCD-03299; Component_Country_Of_Origin: China; ID: 2474; Order_Code_RS: 9402047; ShowFields: YES
C107 = MCD-00097: Capacitor, MLCC, 4.7uF, 16V, X5R, 20%, 0603, T=0,8mm; Manufacturer_Part_Number: GRM188R61C475KE11; Manufacturer: MURATA; Alternate_Manufacturer_Part_Number: GRM188R61C475MAAJ; Part_Preference: Recommended; ECCN_US: EAR99; ECCN_EU: NEC; Provided_By: SUBCO; Component_Country_Of_Origin: Japan; ID: 2767; ShowFields: YES
C123 = MCD-01722: Capacitor, 1uF, 10V, X5R, 10%, 0402, T=0.5mm; Manufacturer_Part_Number: CC0402KRX5R6BB105; Manufacturer: YAGEO; Part_Preference: Recommended; Provided_By: SUBCO; Component_Country_Of_Origin: China; ID: 3822; ShowFields: YES
C137 = MCD-01356: Capacitor, MLCC, 4.7uF, 6V3, X5R, 20%, 0402, T=0,5mm; Manufacturer_Part_Number: GRM155R60J475ME47; Manufacturer: MURATA; Part_Preference: Recommended; ECCN_US: EAR99; ECCN_EU: NEC; Provided_By: SUBCO; Component_Country_Of_Origin: Japan; ID: 3456; Order_Code_RS: 814-5230; ShowFields: YES
HW14 = MCD-00043: SHUNT 2.54mm BLACK; Manufacturer_Part_Number: SNT-100-BK-G; Manufacturer: SAMTEC; Part_Type: Misc; Alternate_Manufacturer_Part_Number: 316102S111A; Alternate_Manufacturer: JIUBABA; Full_Alternate_Internal_Part_Number: MCD-02388; Part_Preference: Recommended; Partial_Alternate_Internal_Part_Number: MCD-01849; Provided_By: SUBCO; Value: SNT-100-BK-G; Alternate_EMS: A; Component_Country_Of_Origin: China, Costa Rica, Malaysia, United States, Vietnam; ID: 2551; ShowFields: YES
JP1 = MCD-00683: Header, 2x1, 2,54mm, VR, TH, Height 5.84mm/2.54mm - Shunt Fitted by default; Part_Type: Connector; Manufacturer_Part_Number: TSW-102-07-G-S; Manufacturer: SAMTEC; Full_Alternate_Internal_Part_Number: MCD-02389; Part_Preference: Recommended; Partial_Alternate_Internal_Part_Number: MCD-02957; Provided_By: SUBCO; Alternate_EMS: A; Component_Country_Of_Origin: China, Costa Rica, Malaysia, United States, Vietnam; ID: 3057; Order_Code_RS: 155-5312; ShowFields: YES
L2 = MCD-03956: Ferrite bead, 18R @ 100MHz, 750mA, 0R004, 0603, T=1mm; Manufacturer_Part_Number: LSMCA160808T180NGR; Manufacturer: TAIYO YUDEN; Part_Preference: Recommended; Component_Country_Of_Origin: Unknown; ID: 6072; ShowFields: YES
L3 = MCD-01110: Inductor 2.2uH, 2x1.6x0.9mm; Manufacturer_Part_Number: LQM2MPN2R2NG0; Manufacturer: MURATA; Part_Preference: Recommended; Provided_By: SUBCO; Component_Country_Of_Origin: Japan; ID: 3384; ShowFields: YES
L5 = MCD-00047: SMD Chip ferrite bead, 600R@100MHz +/-25%, 350mA, 500mohm DC, 0603, T=0.8mm; Part_Type: Inductor; Manufacturer: TAI-TECH; Part_Preference: Recommended; Partial_Alternate_Internal_Part_Number: MCD-02959; Provided_By: SUBCO; Component_Country_Of_Origin: Unknown; ID: 2546; ShowFields: YES
R16 = MCD-00166: Resistor,120K,0402,1%,1/16W; Manufacturer_Part_Number: RC0402FR-07120KL; Manufacturer: YAGEO; Part_Preference: Recommended; Provided_By: SUBCO; Component_Country_Of_Origin: China; ID: 2703; ShowFields: YES
R139 = MCD-00056: Resistor,0R,0603,5%,1/10W; Manufacturer_Part_Number: RC0603JR-070RL; Manufacturer: YAGEO; Part_Preference: Recommended; ECCN_US: EAR99; ECCN_EU: NEC; Provided_By: SUBCO; Component_Country_Of_Origin: China; ID: 2536; ShowFields: YES
SB1-SB3 SB11 SB13 SB16 SB18-SB22 = MCD-00071: Solder Bridge ON; Part_Type: Misc; Manufacturer_Part_Number: RC0603JR-070RL; Manufacturer: YAGEO; Part_Preference: Recommended; Provided_By: SUBCO; ID: 2521; ShowFields: YES
TP1 TP2 TP4 TP5 = MCD-00630: Test Point 0.3mm; Part_Type: Misc; Part_Preference: Recommended; ID: 3115; ShowFields: YES
U1 = MCD-01138: IC VREF SERIES 2.5V 8VSSOP; Manufacturer: TEXAS INSTRUMENTS; Part_Preference: Recommended; Provided_By: SUBCO; Component_Country_Of_Origin: Thailand; ID: 3357; ShowFields: YES
U6 = MCD-01673: STM32H725IGK6 MCU, Cut1.0, 10x10x0.6mm, Pitch0.65mm, Int SMPS; Part_Type: IC; Manufacturer: STMICROELECTRONICS; Manufacturer_HQ_COO: EU; Part_Preference: Recommended; ECCN_US: 3A991A2; ECCN_EU: NEC; Provided_By: SUBCO with ST control; Component_Country_Of_Origin: Taiwan; ID: 3773; ShowFields: YES
U14 = MCD-00078: Ultra low drop-low noise BiCMOS voltage, regulators low ESR capacitors compatible; Part_Type: IC; Manufacturer: STMICROELECTRONICS; BMS_Part_Number: 9176159; Manufacturer_HQ_COO: EU; Part_Preference: Recommended; ECCN_US: EAR99; ECCN_EU: NEC; Provided_By: SUBCO with ST control; Component_Country_Of_Origin: Malaysia; ID: 2516; ShowFields: YES
U15 = MCD-00088: IC REG LDO 5V 0.8A SOT223; Manufacturer: STMICROELECTRONICS; BMS_Part_Number: 9176133; Manufacturer_HQ_COO: EU; Part_Preference: Recommended; Provided_By: SUBCO with ST control; Component_Country_Of_Origin: China; ID: 2503; ShowFields: YES
U17 = MCD-01127: IC REG LDO 3.3V 1.3A 6DFN; Manufacturer: STMICROELECTRONICS; BMS_Part_Number: 9176247; Manufacturer_HQ_COO: EU; Part_Preference: Recommended; Provided_By: SUBCO with ST control; Component_Country_Of_Origin: Malaysia; ID: 3368; ShowFields: YES

## Sheet TAG.SchDoc: TAG
size A4; Date: Not used; ApprovedBy: Not used; CheckedBy: Not used; Author: Not used; CompanyName: STMicroelectronics; DrawnBy: Not used; Engineer: Not used; Organization: Not used; Address1: Not used; Address2: Not used; Address3: Not used; Address4: Not used; DocumentNumber: Not used; Revision: Not used; SheetNumber: 15; SheetTotal: 19
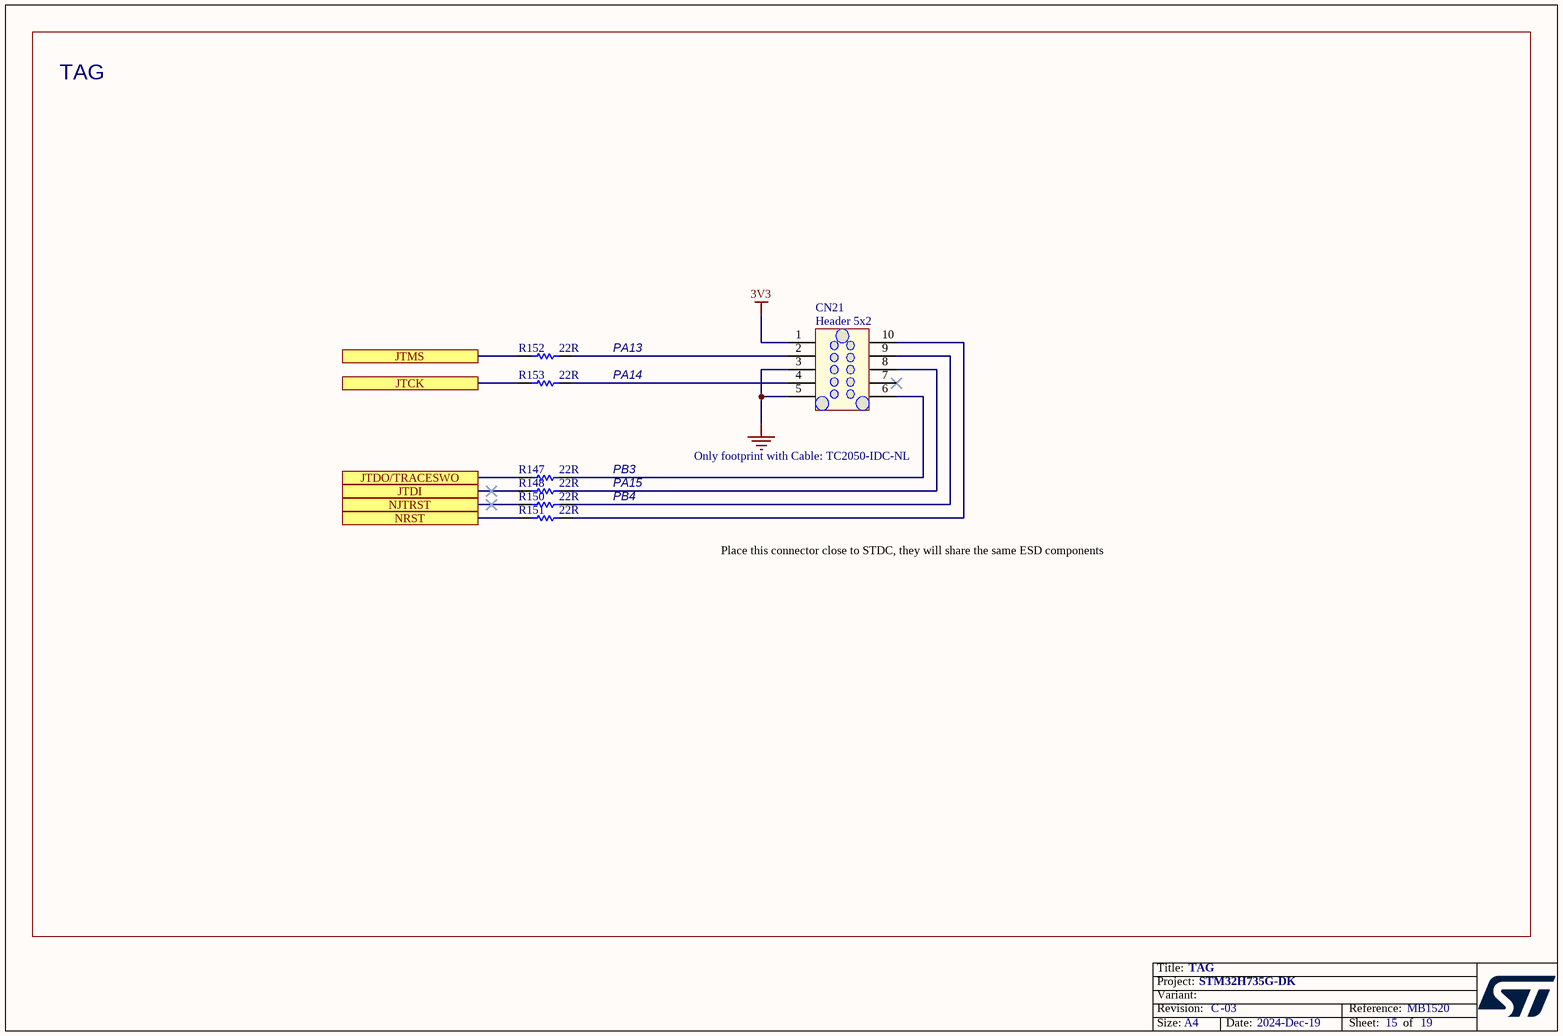
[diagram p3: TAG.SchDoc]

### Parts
CN21  value Header 5x2  [CON_TAG-C_TC2050-IDC-NL]  (hidden comment: Tag-10-C)
R147  value 22R  [R0402]  (hidden comment: Resistor)
R148  value 22R  [R0402]  (hidden comment: Resistor)
R150  value 22R  [R0402]  (hidden comment: Resistor)
R151  value 22R  [R0402]  (hidden comment: Resistor)
R152  value 22R  [R0402]  (hidden comment: Resistor)
R153  value 22R  [R0402]  (hidden comment: Resistor)

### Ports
JTCK, JTDI, JTDO/TRACESWO, JTMS, NJTRST, NRST

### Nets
3V3: CN21.1
GND: CN21.3 CN21.5  [project net POE7]
NJTRST: R150.1 ; port NJTRST
RESET: R151.1 ; port NRST
T_JTDI: R148.1 ; port JTDI
T_SWCLK: R153.1 ; port JTCK
T_SWDIO: R152.1 ; port JTMS
T_SWO: R147.1 ; port JTDO/TRACESWO
NetCN21_2: CN21.2 R152.2
NetCN21_4: CN21.4 R153.2
NetCN21_6: CN21.6 R147.2
NetCN21_8: CN21.8 R148.2
NetCN21_9: CN21.9 R150.2
NetCN21_10: CN21.10 R151.2

Not connected (* = marked no-connect by the designer): CN21 7*

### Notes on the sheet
- TAG
- PA13
- PA14
- PB3
- PA15
- PB4
- Only footprint with Cable: TC2050-IDC-NL
- Place this connector close to STDC, they will share the same ESD components

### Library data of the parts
CN21 = MCD-00031: Tag_Connector Header, 10x2, No legs; Part_Preference: Recommended; Provided_By: SUBCO; ID: 2486; ShowFields: YES
R147 R148 R150-R153 = MCD-00189: Resistor,22R,0402,1%,1/16W; Manufacturer_Part_Number: RC0402FR-0722RL; Manufacturer: YAGEO; Part_Preference: Recommended; Provided_By: SUBCO; Component_Country_Of_Origin: China; ID: 2677; ShowFields: YES

## Sheet Audio.SchDoc: Audio
size A4; Date: Not used; ApprovedBy: Not used; CheckedBy: Not used; Author: Not used; CompanyName: STMicroelectronics; DrawnBy: Not used; Engineer: Not used; Organization: Not used; Address1: Not used; Address2: Not used; Address3: Not used; Address4: Not used; DocumentNumber: Not used; Revision: Not used; SheetNumber: 13; SheetTotal: 19
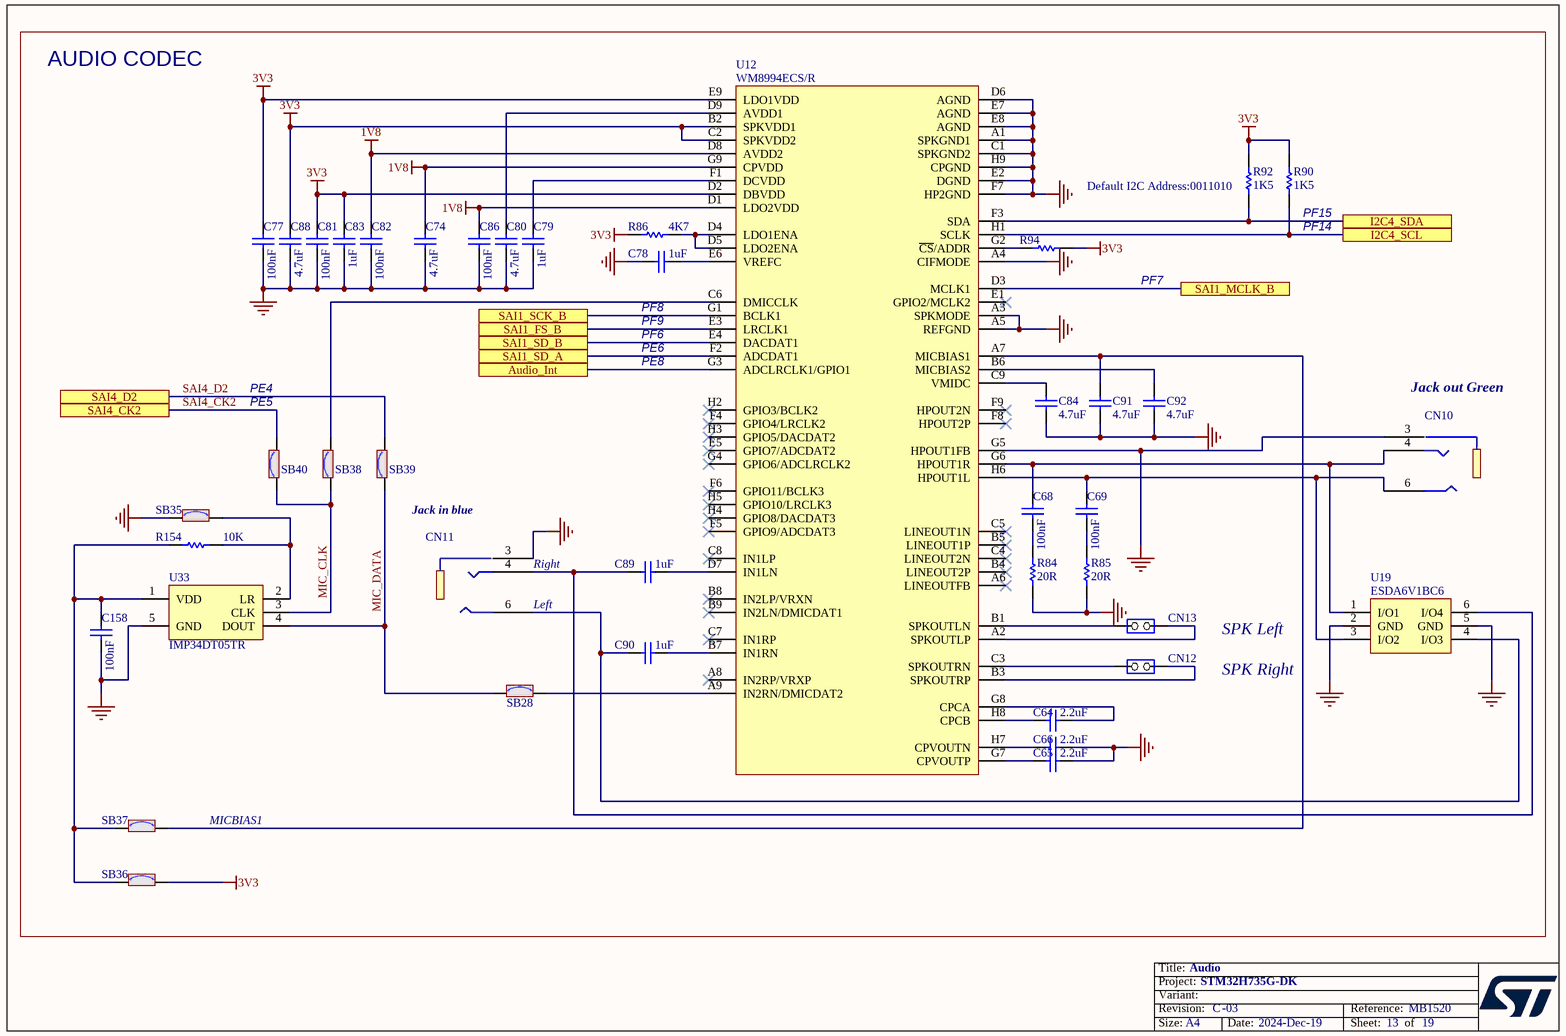
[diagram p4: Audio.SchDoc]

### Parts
C64  value 2.2uF  [C0603]  (hidden comment: Capacitor)
C65  value 2.2uF  [C0603]  (hidden comment: Capacitor)
C66  value 2.2uF  [C0603]  (hidden comment: Capacitor)
C68  value 100nF  [C0402]  (hidden comment: Capacitor)
C69  value 100nF  [C0402]  (hidden comment: Capacitor)
C74  value 4.7uF  [C0603]  (hidden comment: Capacitor)
C77  value 100nF  [C0402]  (hidden comment: Capacitor)
C78  value 1uF  [C0603]  (hidden comment: Capacitor)
C79  value 1uF  [C0603]  (hidden comment: Capacitor)
C80  value 4.7uF  [C0603]  (hidden comment: Capacitor)
C81  value 100nF  [C0402]  (hidden comment: Capacitor)
C82  value 100nF  [C0402]  (hidden comment: Capacitor)
C83  value 1uF  [C0603]  (hidden comment: Capacitor)
C84  value 4.7uF  [C0603]  (hidden comment: Capacitor)
C86  value 100nF  [C0402]  (hidden comment: Capacitor)
C88  value 4.7uF  [C0603]  (hidden comment: Capacitor)
C89  value 1uF  [C0603]  (hidden comment: Capacitor)
C90  value 1uF  [C0603]  (hidden comment: Capacitor)
C91  value 4.7uF  [C0603]  (hidden comment: Capacitor)
C92  value 4.7uF  [C0603]  (hidden comment: Capacitor)
C158  value 100nF  [C0402]  (hidden comment: Capacitor)
CN10  Jack_PJ3028B-3_3P  [CON_PHONE-JACK-3P5_HY_PJ3028B]  (value not drawn)
CN11  Jack_PJ3028B-3_3P  [CON_PHONE-JACK-3P5_HY_PJ3028B]  (value not drawn)
CN12  Jumper_Header 2x1  [CON_SAMTEC_TSW-102-07-G-S]  (value not drawn)
CN13  Jumper_Header 2x1  [CON_SAMTEC_TSW-102-07-G-S]  (value not drawn)
R84  value 20R  [R0603]  (hidden comment: Resistor)
R85  value 20R  [R0603]  (hidden comment: Resistor)
R86  value 4K7  [R0603]  (hidden comment: Resistor)
R90  value 1K5  [R0402]  (hidden comment: Resistor)
R92  value 1K5  [R0402]  (hidden comment: Resistor)
R94  Resistor  [R0402]  (value not drawn)
R154  value 10K  [R0402]  (hidden comment: Resistor)
SB28  SB_ON  [SOLDER-BRIDGE_R0603-0R]  (value not drawn)
SB35  SB_ON  [SOLDER-BRIDGE_R0603-0R]  (value not drawn)
SB36  SB_ON  [SOLDER-BRIDGE_R0603-0R]  (value not drawn)
SB37  SB_ON  [SOLDER-BRIDGE_R0603-0R]  (value not drawn)
SB38  SB_ON  [SOLDER-BRIDGE_R0603-0R]  (value not drawn)
SB39  SB_ON  [SOLDER-BRIDGE_R0603-0R]  (value not drawn)
SB40  SB_ON  [SOLDER-BRIDGE_R0603-0R]  (value not drawn)
U12  WM8994ECS/R  [ICC_W-CSP-BGA72_4P511X4P023_P050]
U19  ESDA6V1BC6  [ESD_SOT23-6L]
U33  IMP34DT05TR  [MIC_HCLGA_3X4X1_4LD]

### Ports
Audio_Int, I2C4_SCL, I2C4_SDA, SAI1_FS_B, SAI1_MCLK_B, SAI1_SCK_B, SAI1_SD_A, SAI1_SD_B, SAI4_CK2, SAI4_D2

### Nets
1V8: C74.2 C82.1 C86.1 U12.D1(LDO2VDD) U12.D8(AVDD2) U12.G9(CPVDD)
3V3: C77.1 C81.1 C83.2 C88.2 R86.1 R90.2 R92.2 R94.1 SB36.2 U12.B2(SPKVDD1) U12.C2(SPKVDD2) U12.D2(DBVDD) U12.E9(LDO1VDD)
GND: C65.1 C66.1 C74.1 C77.2 C78.2 C79.1 C80.1 C81.2 C82.2 C83.1 C84.1 C86.2 C88.1 C91.1 C92.1 C158.2 CN10.3 CN11.3 R84.1 R85.1 SB35.1 U12.A1(SPKGND1) U12.A3(SPKMODE) U12.A4(CIFMODE) U12.A5(REFGND) U12.C1(SPKGND2) U12.D6(AGND) U12.E2(DGND) U12.E7(AGND) U12.E8(AGND) U12.F7(HP2GND) U12.G5(HPOUT1FB) U12.H9(CPGND) U19.2(GND) U19.5(GND) U33.5(GND)  [project net POE7]
Audio_Int: U12.G3(ADCLRCLK1/GPIO1) ; port Audio_Int
I2C4_SCL: R90.1 U12.H1(SCLK) ; port I2C4_SCL
I2C4_SDA: R92.1 U12.F3(SDA) ; port I2C4_SDA
MIC_CLK: SB38.1 SB40.1 U33.3(CLK)
MIC_DATA: SB28.1 SB39.1 U33.4(DOUT)
SAI1_FS_B: U12.E3(LRCLK1) ; port SAI1_FS_B
SAI1_MCLK_B: U12.D3(MCLK1) ; port SAI1_MCLK_B
SAI1_SCK_B: U12.G1(BCLK1) ; port SAI1_SCK_B
SAI1_SD_A: U12.F2(ADCDAT1) ; port SAI1_SD_A
SAI1_SD_B: U12.E4(DACDAT1) ; port SAI1_SD_B
SAI4_CK2: SB40.2 ; port SAI4_CK2
SAI4_D2: SB39.2 ; port SAI4_D2
NetC64_1: C64.1 U12.G8(CPCA)
NetC64_2: C64.2 U12.H8(CPCB)
NetC65_2: C65.2 U12.G7(CPVOUTP)
NetC66_2: C66.2 U12.H7(CPVOUTN)
NetC68_1: C68.1 CN10.4 U12.G6(HPOUT1R) U19.1(I/O1)
NetC68_2: C68.2 R84.2
NetC69_1: C69.1 CN10.6 U12.H6(HPOUT1L) U19.3(I/O2)
NetC69_2: C69.2 R85.2
NetC78_1: C78.1 U12.E6(VREFC)
NetC79_2: C79.2 U12.F1(DCVDD)
NetC80_2: C80.2 U12.D9(AVDD1)
NetC84_2: C84.2 U12.C9(VMIDC)
NetC89_1: C89.1 U12.D7(IN1LN)
NetC89_2: C89.2 CN11.4 U19.6(I/O4)
NetC90_1: C90.1 U12.B7(IN1RN)
NetC90_2: C90.2 CN11.6 U19.4(I/O3)
NetC91_2: C91.2 SB37.2 U12.A7(MICBIAS1)
NetC92_2: C92.2 U12.B6(MICBIAS2)
NetC158_1: C158.1 R154.2 SB36.1 SB37.1 U33.1(VDD)
NetCN12_1: CN12.1(COMMON) U12.B3(SPKOUTRP)
NetCN12_2: CN12.2(NO) U12.C3(SPKOUTRN)
NetCN13_1: CN13.1(COMMON) U12.A2(SPKOUTLP)
NetCN13_2: CN13.2(NO) U12.B1(SPKOUTLN)
NetR86_2: R86.2 U12.D4(LDO1ENA) U12.D5(LDO2ENA)
NetR94_2: R94.2 U12.G2(~{CS}/ADDR)
NetR154_1: R154.1 SB35.2 U33.2(LR)
NetSB28_2: SB28.2 U12.A9(IN2RN/DMICDAT2)
NetSB38_2: SB38.2 U12.C6(DMICCLK)

Not connected (* = marked no-connect by the designer): U12 A6(LINEOUTFB)* A8(IN2RP/VRXP)* B4(LINEOUT2P)* B5(LINEOUT1P)* B8(IN2LP/VRXN)* B9(IN2LN/DMICDAT1)* C4(LINEOUT2N)* C5(LINEOUT1N)* C7(IN1RP)* C8(IN1LP)* E1(GPIO2/MCLK2)* E5(GPIO7/ADCDAT2)* F4(GPIO4/LRCLK2)* F5(GPIO9/ADCDAT3)* F6(GPIO11/BCLK3)* F8(HPOUT2P)* F9(HPOUT2N)* G4(GPIO6/ADCLRCLK2)* H2(GPIO3/BCLK2)* H3(GPIO5/DACDAT2)* H4(GPIO8/DACDAT3)* H5(GPIO10/LRCLK3)*

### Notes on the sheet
- AUDIO CODEC
- (near R92) Default I2C Address:0011010
- (near R90) PF15
- (near R90) PF14
- (near C78) PF8
- PF7
- PF6
- PF9
- PE8
- PE6
- PE4
- (near SB40) PE5
- (near CN10) Jack out Green
- Jack in blue
- (near CN11) Right
- (near CN11) Left
- SPK Left
- SPK Right
- MICBIAS1

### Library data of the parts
C64-C66 = MCD-00012: as C22 on sheet STM32_microcontroller_Power
C68 C69 C77 C81 C82 C86 C158 = MCD-00006: as C95 on sheet STM32_microcontroller_Power
C74 C80 C84 C88 C91 C92 = MCD-00009: Capacitor, MLCC, 4.7uF, 16V, X5R, 10%, 0603, T=0.8mm; Manufacturer_Part_Number: CC0603KRX5R7BB475; Manufacturer: YAGEO; Part_Preference: Recommended; Partial_Alternate_Internal_Part_Number: MCD-03565; Provided_By: SUBCO; Alternate_EMS: A; Component_Country_Of_Origin: China; ID: 2471; ShowFields: YES
C78 C79 C83 C89 C90 = MCD-00010: as C21 on sheet STM32_microcontroller_Power
CN10 = MCD-00018: Connector Jack socket Stereo 3.5mm, 3 pins, RA, SMT, Green (Line output); Manufacturer_Part_Number: PJ3028B-3_GR; Manufacturer: QIAOD; Alternate_Manufacturer_Part_Number: PJ30280-3_GR; Part_Preference: Recommended; Value: Jack_Socket-Stereo_PJ3028B-3_GR; Provided_By: SUBCO; Component_Country_Of_Origin: Unknown; ID: 2498; ShowFields: YES
CN11 = MCD-00682: Connector Jack socket Stereo 3.5mm, 3 pins, RA, SMT, Blue (Line input); Manufacturer_Part_Number: PJ3028B-3_BE; Manufacturer: QIAOD; Alternate_Manufacturer_Part_Number: PJ30280-3_BE; Part_Preference: Recommended; Value: Jack_Socket-Stereo_PJ3028B-3_BE; Provided_By: SUBCO; Component_Country_Of_Origin: Unknown; ID: 3061; ShowFields: YES
CN12 CN13 = MCD-00045: Header, 2x1, 2,54mm, VR, TH, Height 5.84mm/2.54mm; Part_Type: Connector; Manufacturer_Part_Number: TSW-102-07-G-S; Manufacturer: SAMTEC; Alternate_Manufacturer_Part_Number: 313102S111116; Alternate_Manufacturer: JIUBABA; Full_Alternate_Internal_Part_Number: MCD-02390; Part_Preference: Recommended; Partial_Alternate_Internal_Part_Number: MCD-02957; Provided_By: SUBCO; Alternate_EMS: A; Component_Country_Of_Origin: China, Costa Rica, Malaysia, United States, Vietnam; ID: 2545; Order_Code_RS: 155-5312; ShowFields: YES
R84 R85 = MCD-00345: Resistor,20R,0603,1%,1/10W; Manufacturer_Part_Number: RC0603FR-0720RL; Manufacturer: YAGEO; Part_Preference: Recommended; Provided_By: SUBCO; Component_Country_Of_Origin: China; ID: 2933; ShowFields: YES
R86 = MCD-00219: Resistor,4K7,0603,1%,1/10W; Manufacturer_Part_Number: RC0603FR-074K7L; Manufacturer: YAGEO; Part_Preference: Recommended; Provided_By: SUBCO; Component_Country_Of_Origin: China; ID: 2648; ShowFields: YES
R90 R92 = MCD-00068: Resistor,1K5,0402,1%,1/16W; Manufacturer_Part_Number: RC0402FR-071K5L; Manufacturer: YAGEO; Part_Preference: Recommended; Provided_By: SUBCO; Component_Country_Of_Origin: China; ID: 2524; ShowFields: YES
R94 R154 = MCD-00053: Resistor,10K,0402,1%,1/16W; Manufacturer_Part_Number: RC0402FR-0710KL; Manufacturer: YAGEO; BMS_Part_Number: 9131590; Part_Preference: Recommended; Provided_By: SUBCO; Component_Country_Of_Origin: China; ID: 2539; ShowFields: YES
SB28 SB35-SB40 = MCD-00071: as SB1 on sheet STM32_microcontroller_Power
U12 = MCD-00079: Multi-Channel Audio Hub CODEC for Smartphones; Part_Type: IC; Manufacturer: CIRRUS LOGIC; Part_Preference: Recommended; Provided_By: SUBCO; Component_Country_Of_Origin: China; ID: 2513; ShowFields: YES
U19 = MCD-00247: Quad Bidir ESD protection; Part_Type: Diode; Manufacturer: STMICROELECTRONICS; BMS_Part_Number: 9179038; Manufacturer_HQ_COO: EU; Part_Preference: Recommended; Provided_By: SUBCO with ST control; Component_Country_Of_Origin: China; ID: 2624; ShowFields: YES
U33 = MCD-01715: MEMS audio sensor omnidirectional digital microphone for industrial applications; Part_Type: IC; Manufacturer: STMICROELECTRONICS; BMS_Part_Number: 9177995; Manufacturer_HQ_COO: EU; Part_Preference: Recommended; Component_Country_Of_Origin: Philippines; ID: 3815; ShowFields: YES

## Sheet USB_OTG_FS.SchDoc: USB OTG FS
size A4; Date: Not used; ApprovedBy: Not used; CheckedBy: Not used; Author: Not used; CompanyName: STMicroelectronics; DrawnBy: Not used; Engineer: Not used; Organization: Not used; Address1: Not used; Address2: Not used; Address3: Not used; Address4: Not used; DocumentNumber: Not used; Revision: Not used; SheetNumber: 7; SheetTotal: 19
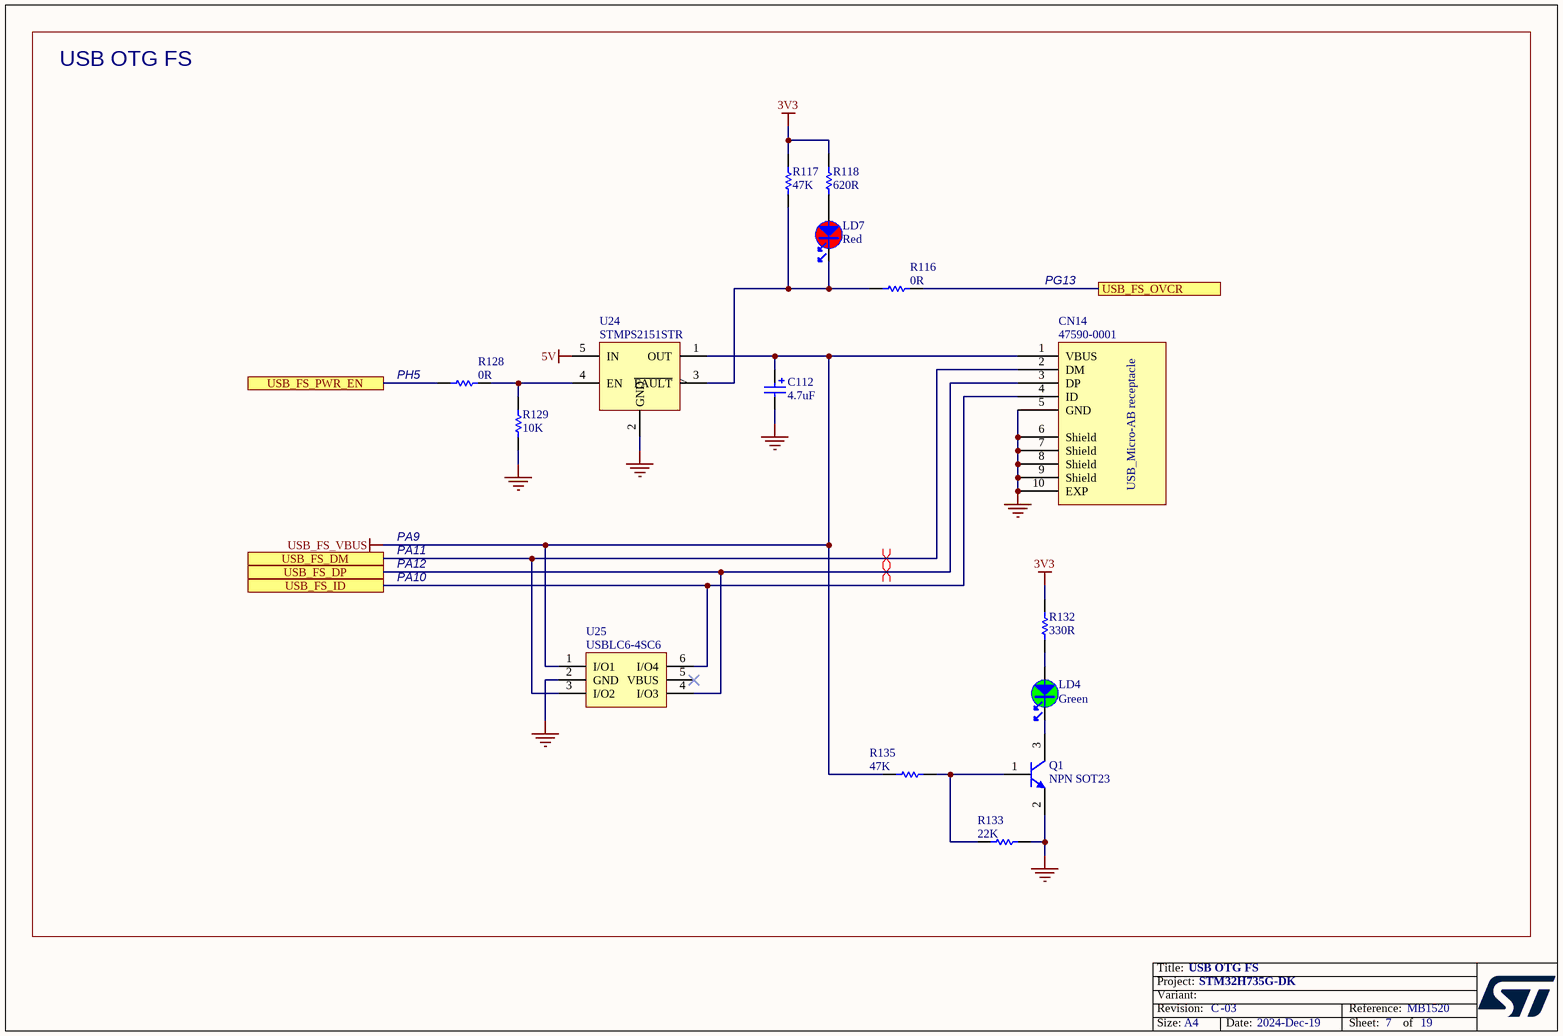
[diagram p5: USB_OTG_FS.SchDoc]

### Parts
C112  value 4.7uF  [CPOL_VISHAY_TANTAL-595D_1407_H220]  (hidden comment: Cap_POL_TANA)
CN14  Manufacturer_Part_Number: 47590-0001  [CON_USBMICROAB_MOLEX_47590-0001_H3]  (hidden comment: USB_uAB_47590.0001)
LD4  value Green  [LED_0603_GREEN]  (hidden comment: LED_green)
LD7  value Red  [LED_0603_RED]  (hidden comment: LED_red)
Q1  value NPN SOT23  [NPN_SOT23]  (hidden comment: 9013-SOT23)
R116  value 0R  [R0402]  (hidden comment: Resistor)
R117  value 47K  [R0402]  (hidden comment: Resistor)
R118  value 620R  [R0402]  (hidden comment: Resistor)
R128  value 0R  [R0402]  (hidden comment: Resistor)
R129  value 10K  [R0402]  (hidden comment: Resistor)
R132  value 330R  [R0402]  (hidden comment: Resistor)
R133  value 22K  [R0402]  (hidden comment: Resistor)
R135  value 47K  [R0402]  (hidden comment: Resistor)
U24  STMPS2151STR  [MOS_SOT23-5L]
U25  USBLC6-4SC6  [ESD_SOT23-6L]

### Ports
USB_FS_DM, USB_FS_DP, USB_FS_ID, USB_FS_OVCR, USB_FS_PWR_EN

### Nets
3V3: R117.2 R118.2 R132.2
5V: U24.5(IN)
GND: C112.2 CN14.5(GND) CN14.6(Shield) CN14.7(Shield) CN14.8(Shield) CN14.9(Shield) CN14.10(EXP) Q1.2(E) R129.1 R133.2 U24.2(GND) U25.2(GND)  [project net POE7]
USB_FS_VBUS: C112.1 CN14.1(VBUS) R135.2 U24.1(OUT) U25.1(I/O1)
USB_FS_DM: CN14.2(DM) U25.3(I/O2) ; port USB_FS_DM
USB_FS_DP: CN14.3(DP) U25.4(I/O3) ; port USB_FS_DP
USB_FS_ID: CN14.4(ID) U25.6(I/O4) ; port USB_FS_ID
USB_FS_OVCR: R116.2 ; port USB_FS_OVCR
USB_FS_PWR_EN: R128.1 ; port USB_FS_PWR_EN
NetLD4_1: LD4.1 R132.1
NetLD4_2: LD4.2 Q1.3(C)
NetLD7_1: LD7.1 R118.1
NetLD7_2: LD7.2 R116.1 R117.1 U24.3(~{FAULT})
NetQ1_1: Q1.1(B) R133.1 R135.1
NetR128_2: R128.2 R129.2 U24.4(EN)

Not connected (* = marked no-connect by the designer): U25 5(VBUS)*

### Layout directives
differential pair: USB_FS_DM, USB_FS_DP

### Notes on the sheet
- USB OTG FS
- PG13
- (near R128) PH5
- PA9
- PA10
- PA11
- PA12

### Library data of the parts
C112 = MCD-00595: Capacitor, Tantalum, 4.7uF, 16V, +/-10%, 595D case A; Manufacturer_Part_Number: 595D475X9016A2T; Manufacturer: VISHAY; Part_Preference: Recommended; Order_Code_RS: 117-303; Provided_By: SUBCO; Component_Country_Of_Origin: Israel; ID: 3146; ShowFields: YES
CN14 = MCD-00022: USB-MICRO-AB, 0.65mm, RA, SMT, Top Mount (compatible with MCD-00661 USB certified); Part_Type: Connector; Manufacturer: MOLEX; Alternate_Manufacturer_Part_Number: ZX62RD-AB-5P8(30); Alternate_Manufacturer: HIROSE; Part_Preference: Recommended; Provided_By: SUBCO; Component_Country_Of_Origin: Unknown; ID: 2495; Order_Code_RS: 702-5481; ShowFields: YES
LD4 = MCD-02900: LED, Green, 2V, 20mA, 0603; Part_Type: Display; Manufacturer_Part_Number: 19-213SYGC/S530-E2/5T; Manufacturer: EVERLIGHT; Part_Preference: Recommended; Full_Alternate_Internal_Part_Number: MCD-00320; Partial_Alternate_Internal_Part_Number: MCD-00050; Component_Country_Of_Origin: China; ID: 5016; ShowFields: YES
LD7 = MCD-02899: LED, Red, 2V35, 20mA, 0603; Manufacturer_Part_Number: 19-213/R6C-AP1Q2B/5T; Manufacturer: EVERLIGHT; Part_Type: Display; Full_Alternate_Internal_Part_Number: MCD-00049; Part_Preference: Recommended; Component_Country_Of_Origin: China; ID: 5015; ShowFields: YES
Q1 = MCD-00073: NPN Bipolar Transistor; Part_Type: IC; Manufacturer_Part_Number: BSR14; Manufacturer: ON SEMICONDUCTOR; Alternate_Manufacturer_Part_Number: MMBT2222ALT1G / MMBT2222ALT3G; Part_Preference: Recommended; Partial_Alternate_Internal_Part_Number: MCD-01737, MCD-03305; Provided_By: SUBCO; Alternate_EMS: M, M; Component_Country_Of_Origin: Unknown; ID: 2519; ShowFields: YES
R116 R128 = MCD-00052: Resistor,0R,0402,5%,1/16W; Manufacturer_Part_Number: RC0402JR-070RL; Manufacturer: YAGEO; Part_Preference: Recommended; Provided_By: SUBCO; Component_Country_Of_Origin: China; ID: 2540; Order_Code_RS: 618-5804; ShowFields: YES
R117 R135 = MCD-00063: Resistor,47K,0402,1%,1/16W; Manufacturer_Part_Number: RC0402FR-0747KL; Manufacturer: YAGEO; Part_Preference: Recommended; Provided_By: SUBCO; Component_Country_Of_Origin: China; ID: 2528; ShowFields: YES
R118 = MCD-00499: Resistor,620R,0402,1%,1/16W; Manufacturer_Part_Number: RC0402FR-07620RL; Manufacturer: YAGEO; Part_Preference: Recommended; Provided_By: SUBCO; Component_Country_Of_Origin: China; ID: 2781; ShowFields: YES
R129 = MCD-00053: as R94 on sheet Audio
R132 = MCD-00062: Resistor,330R,0402,1%,1/16W; Manufacturer_Part_Number: RC0402FR-07330RL; Manufacturer: YAGEO; Part_Preference: Recommended; Provided_By: SUBCO; Component_Country_Of_Origin: China; ID: 2529; ShowFields: YES
R133 = MCD-00429: Resistor,22K,0402,1%,1/16W; Manufacturer_Part_Number: RC0402FR-0722KL; Manufacturer: YAGEO; Part_Preference: Recommended; Provided_By: SUBCO; Component_Country_Of_Origin: China; ID: 2849; ShowFields: YES
U24 = MCD-00159: 500mA, Enhanced single channel power switches with active high enable pin; Part_Type: IC; Manufacturer: STMICROELECTRONICS; Alternate_Manufacturer_Part_Number: TPS2051C; Alternate_Manufacturer: TEXAS INSTRUMENTS; BMS_Part_Number: 9159009; Manufacturer_HQ_COO: EU; Part_Preference: Recommended; Provided_By: SUBCO with ST control; Component_Country_Of_Origin: Malaysia; ID: 2708; Order_Code_RS: 880-5415; ShowFields: YES
U25 = MCD-00250: Very low capacitance ESD protection , 4 lines; Part_Type: IC; Manufacturer: STMICROELECTRONICS; BMS_Part_Number: 9151001; Manufacturer_HQ_COO: EU; Part_Preference: Recommended; Provided_By: SUBCO with ST control; Component_Country_Of_Origin: China; ID: 2616; ShowFields: YES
